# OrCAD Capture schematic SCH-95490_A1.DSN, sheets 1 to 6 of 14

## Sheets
1 01 TITLE PAGE: title: FRDM-MCXE31B; rev: A1; company: NXP Semiconductors; note: SCH-95490 PDF: SPF-95490; note: 6501 William Cannon Drive West; note: Austin, TX 78735-8598
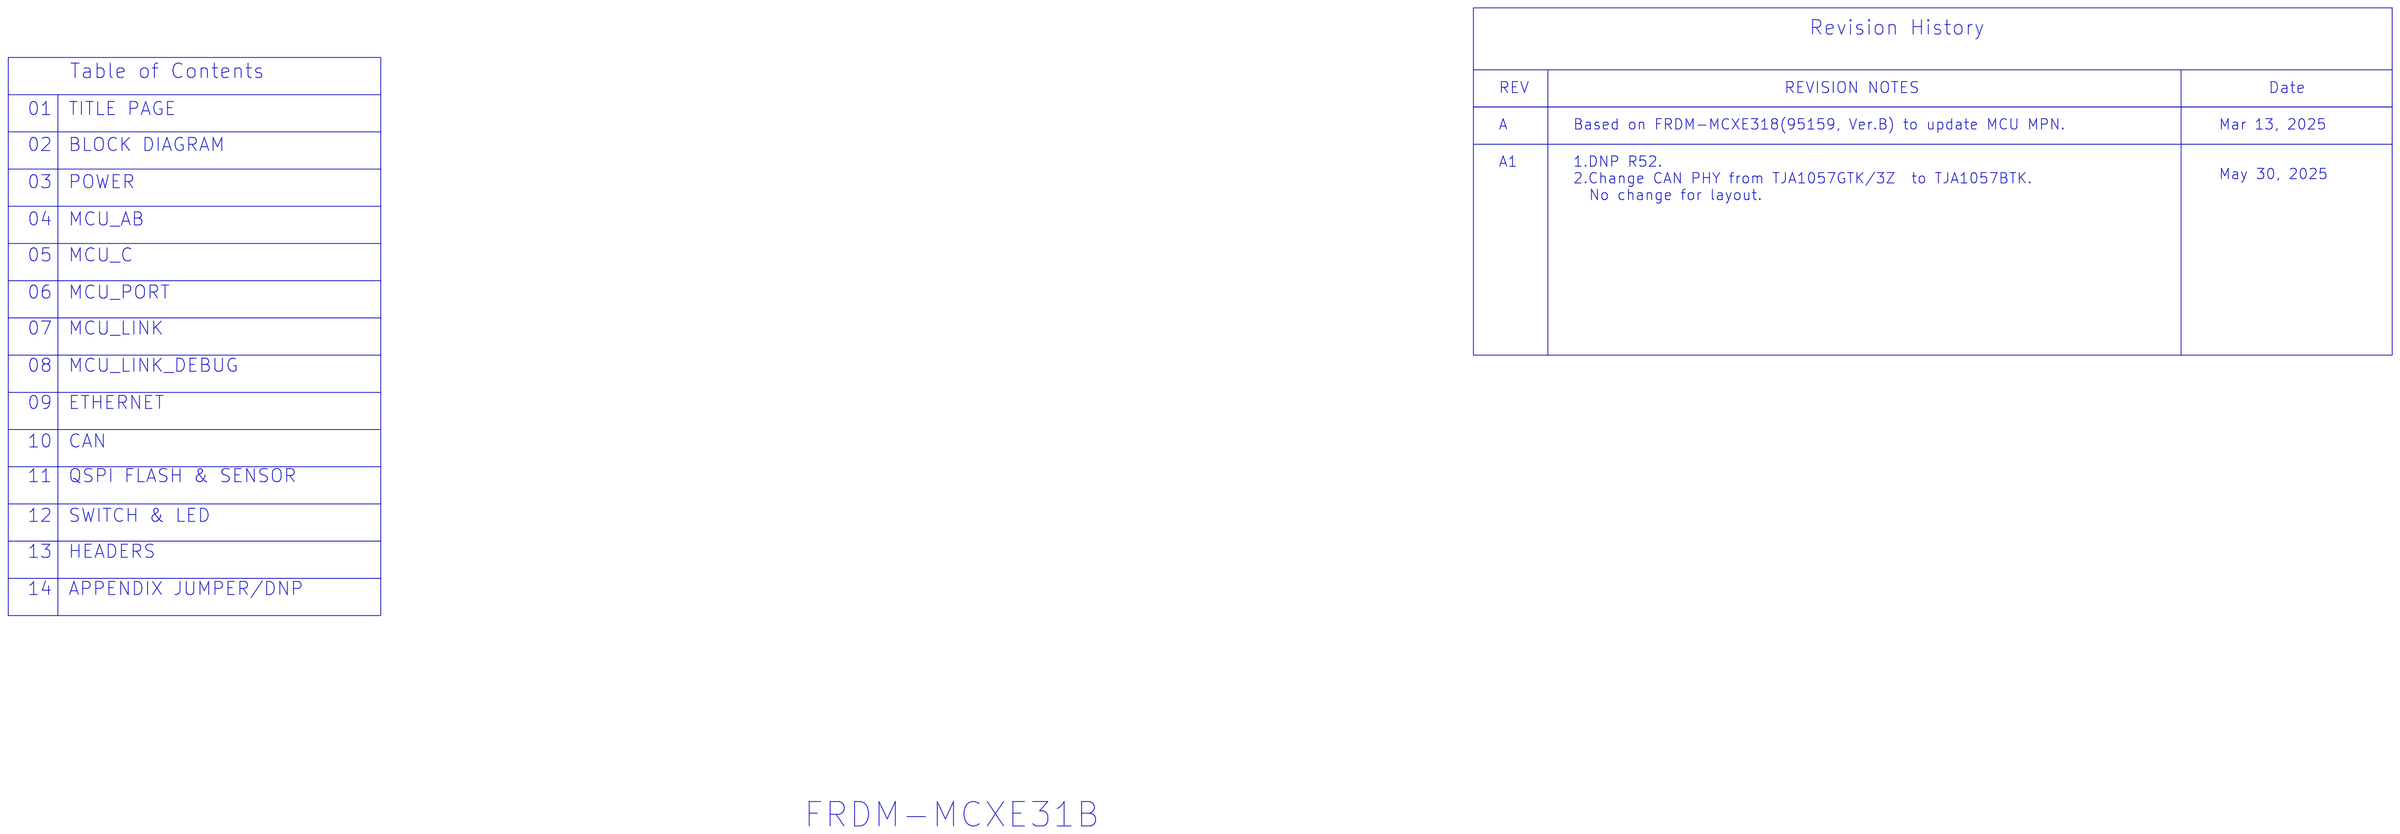
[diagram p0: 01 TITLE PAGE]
2 02 BLOCK DIAGRAM
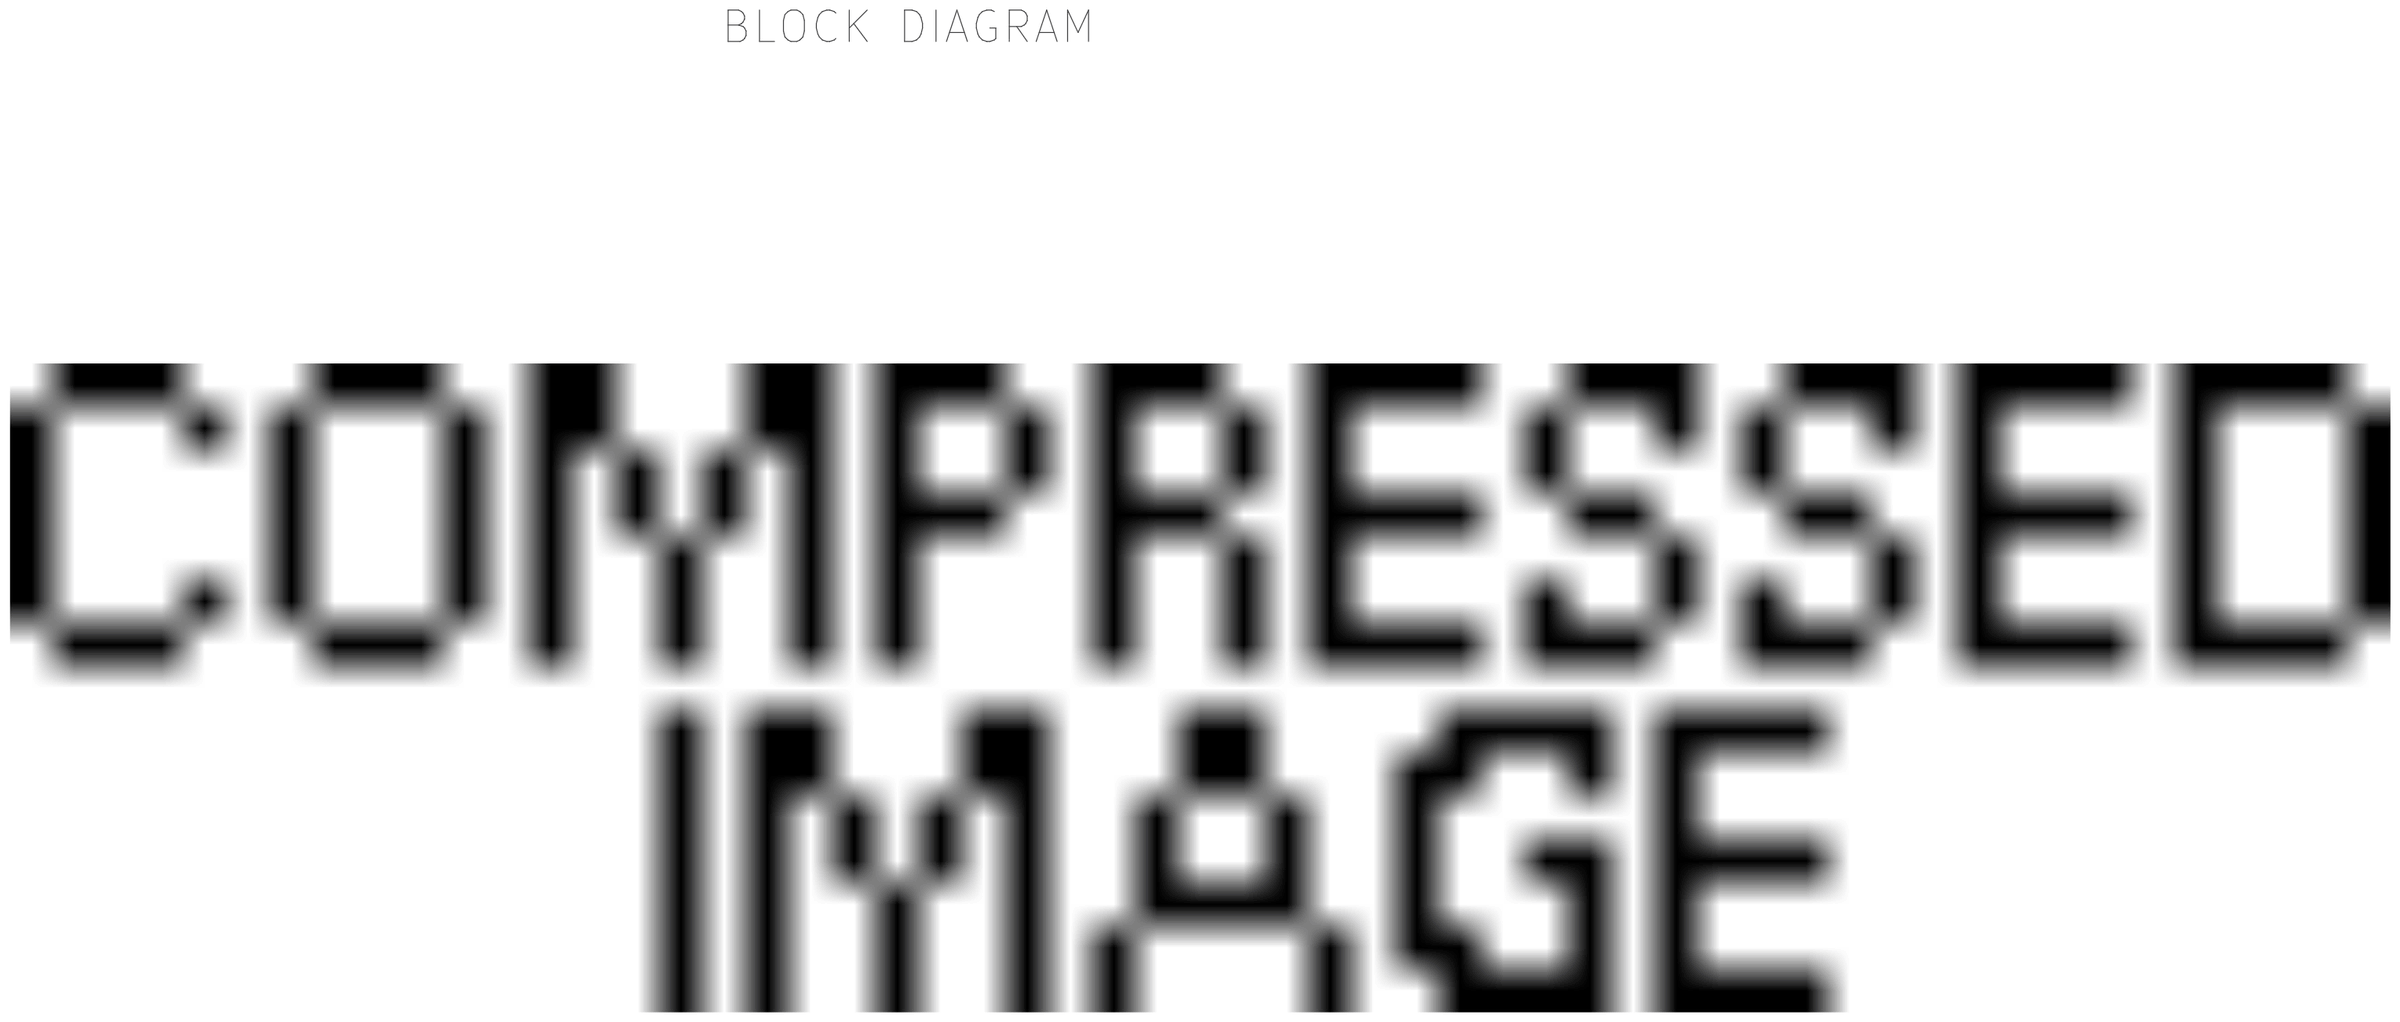
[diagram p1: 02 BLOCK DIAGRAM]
3 03 POWER: size C
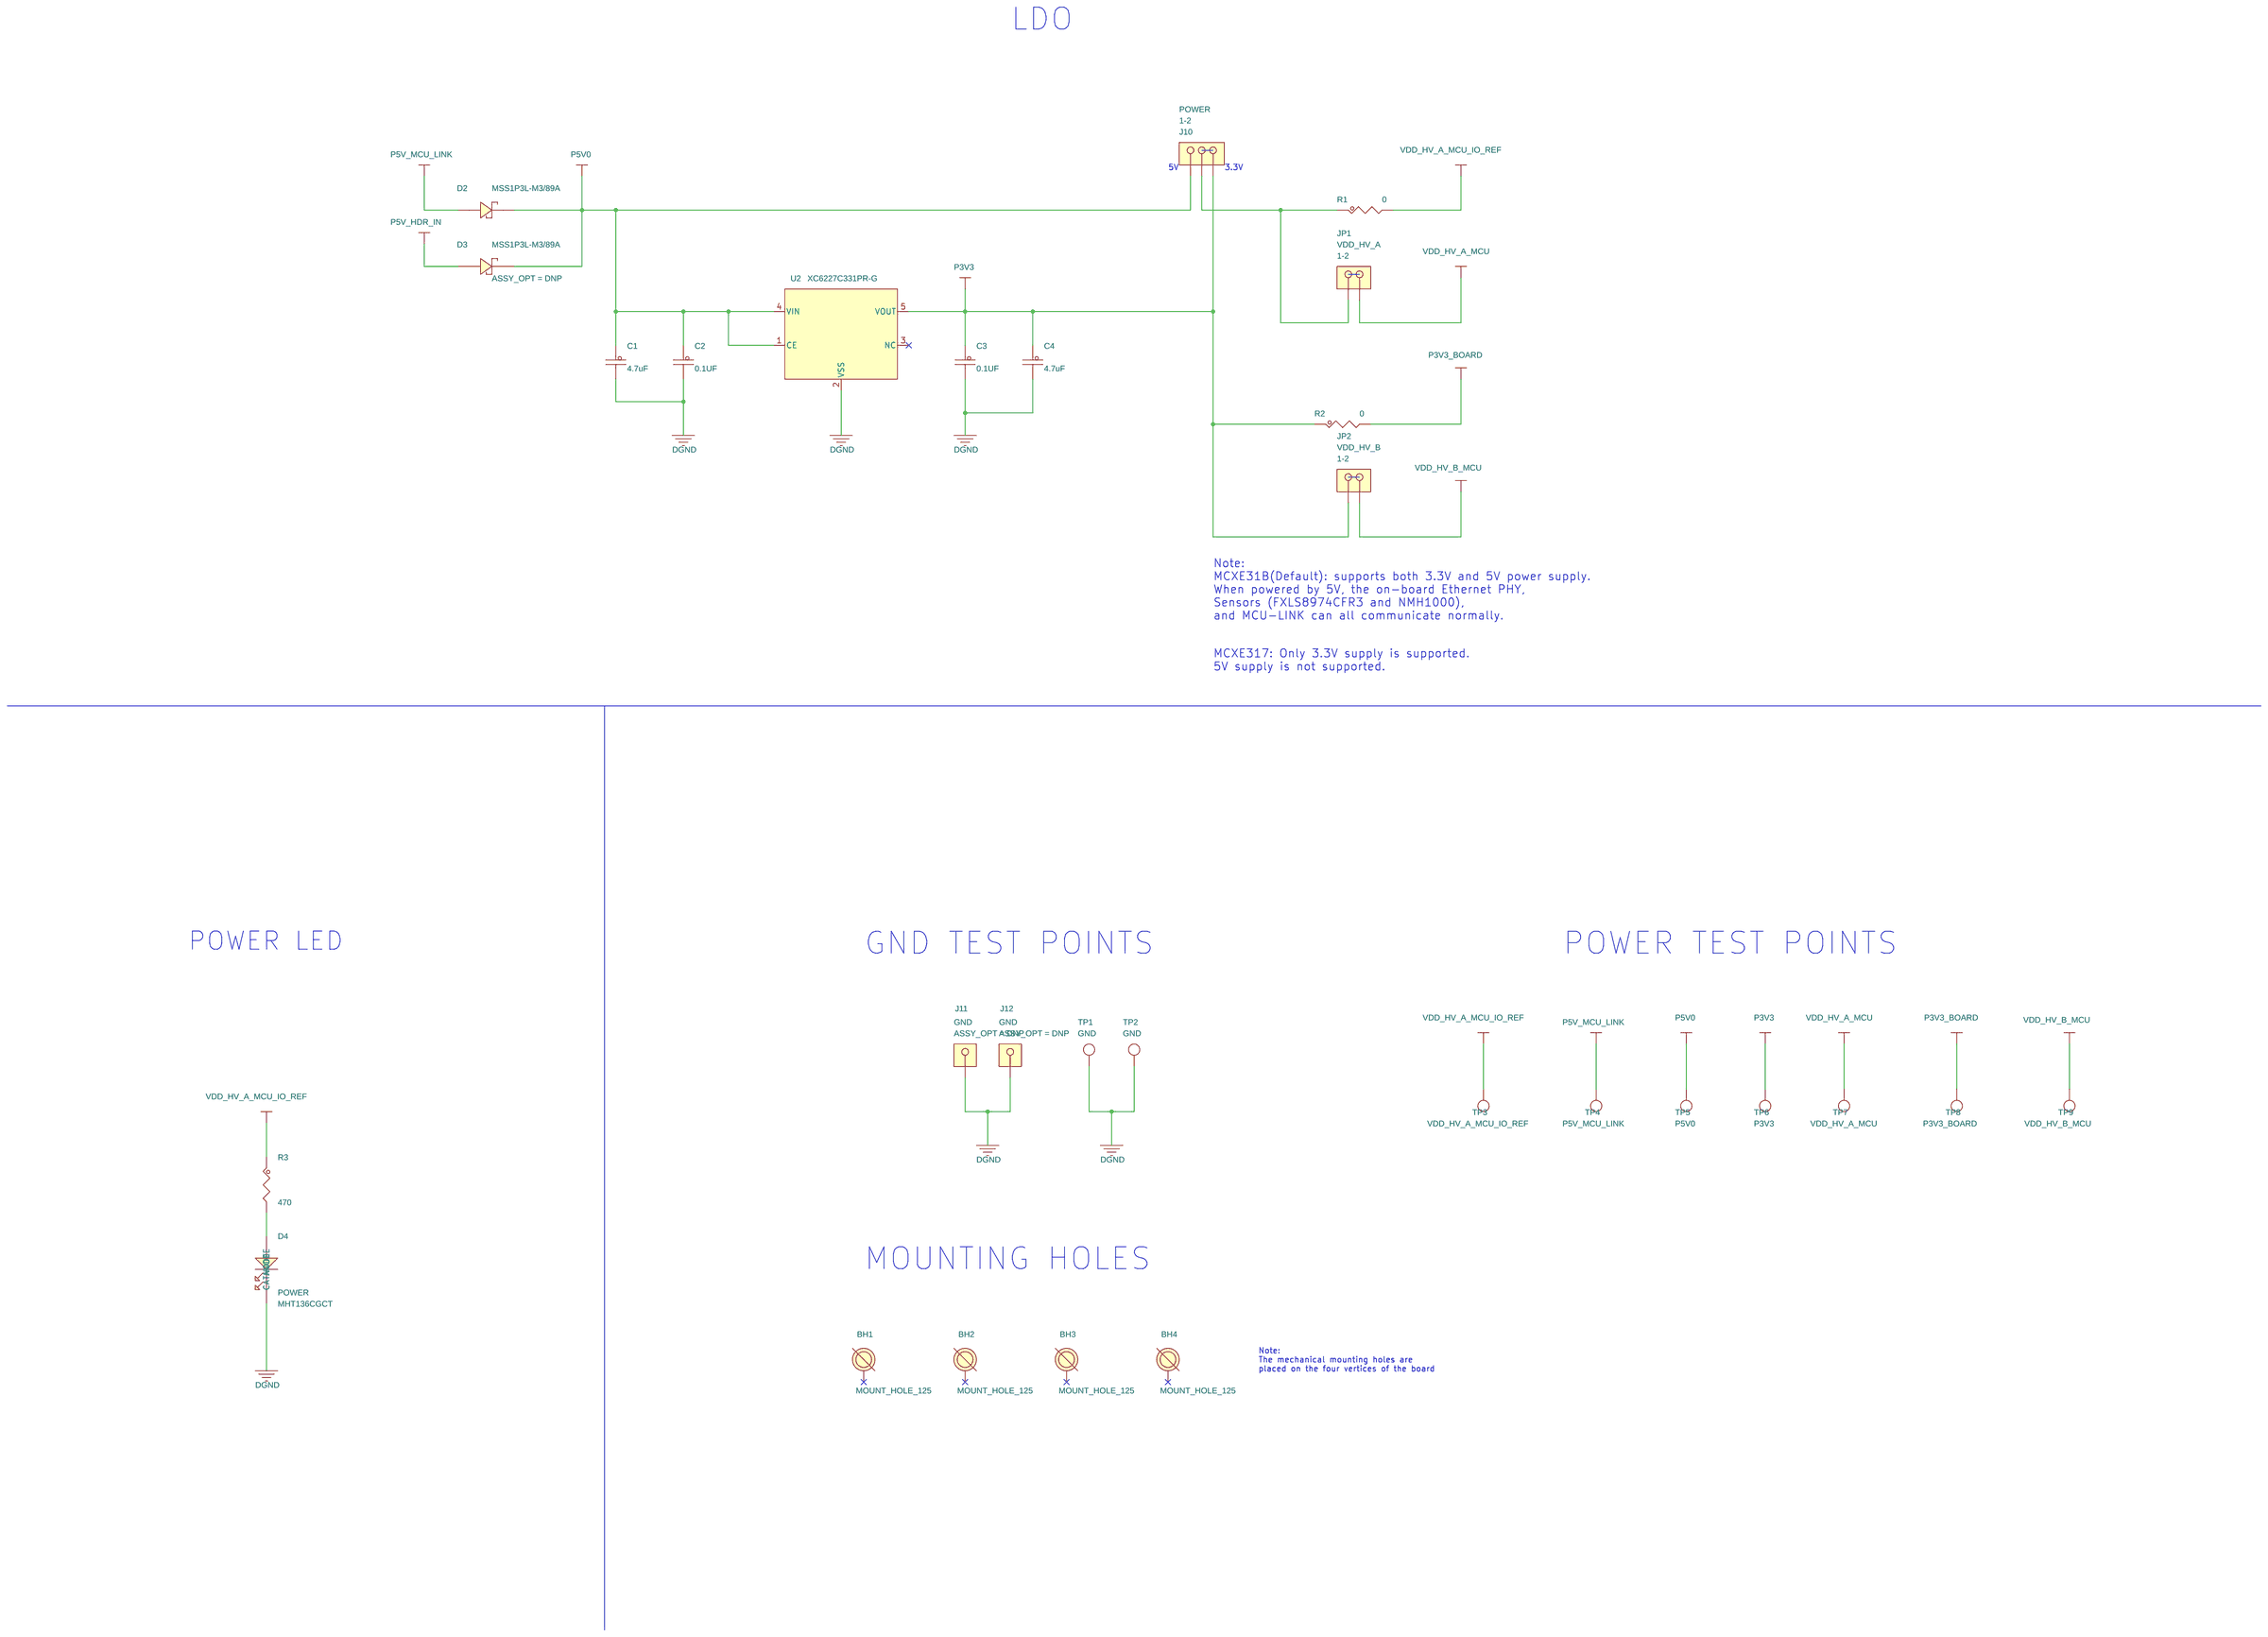
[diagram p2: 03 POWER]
4 04 MCU_AB: size C
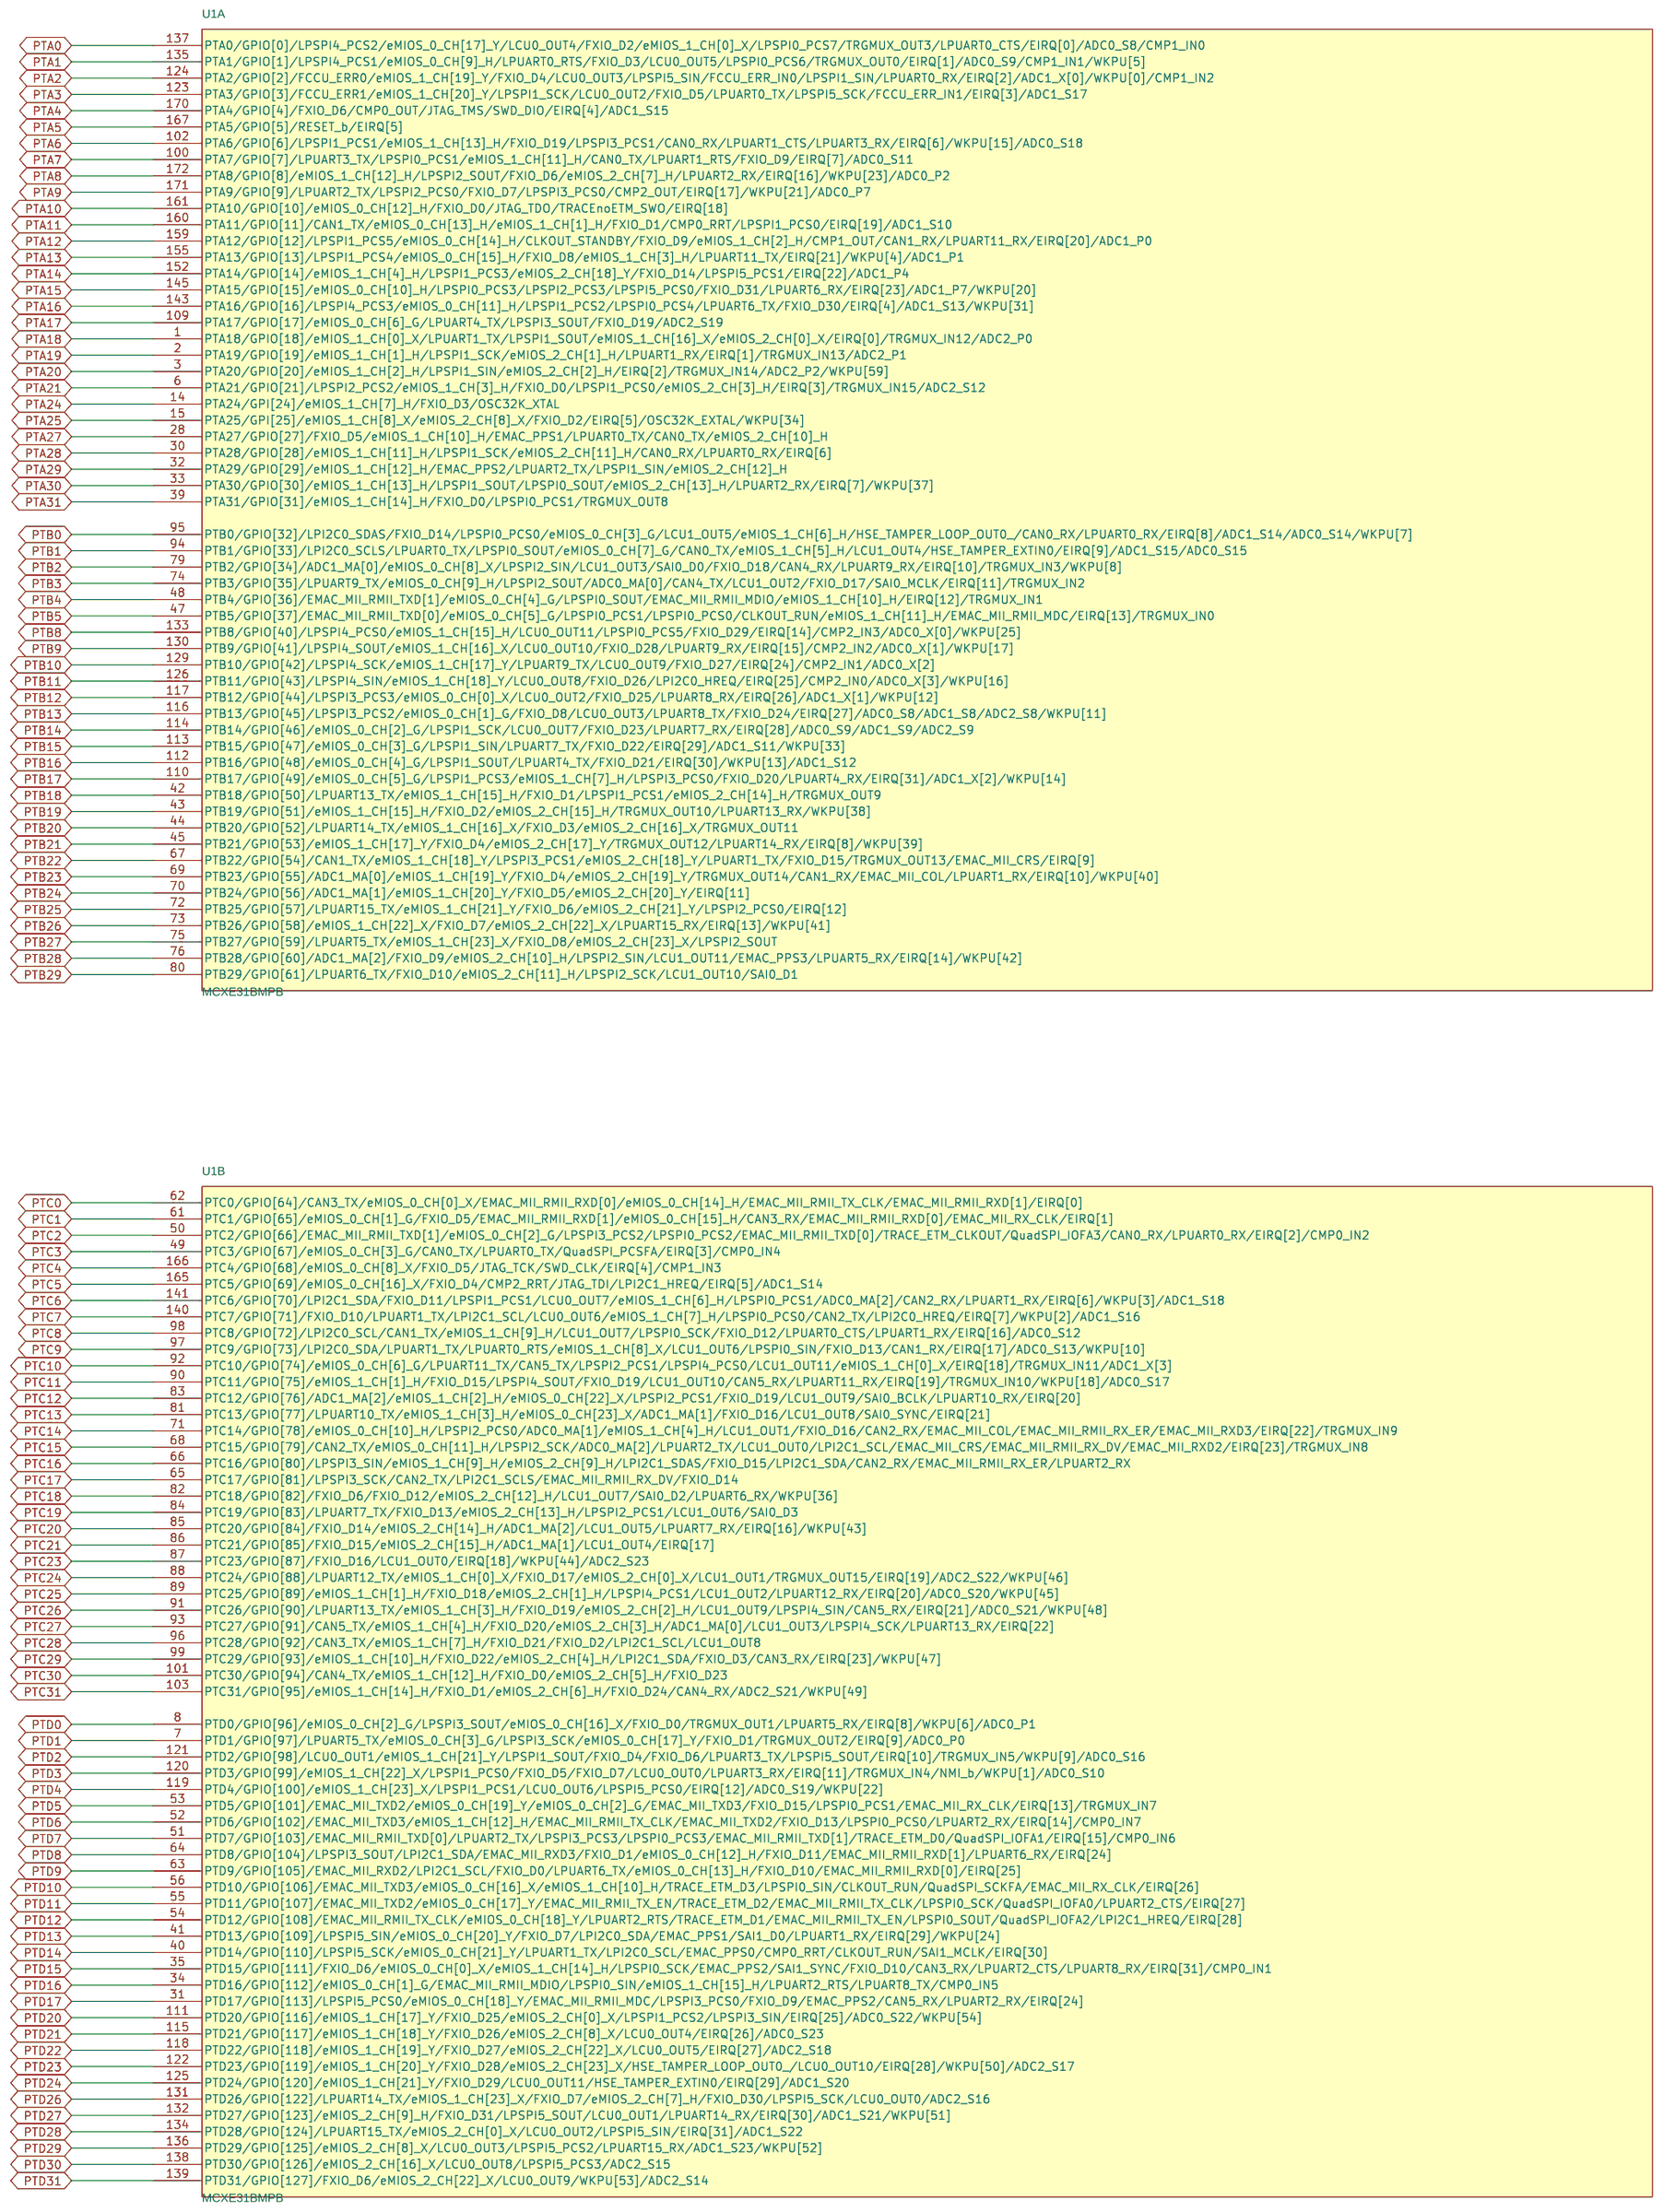
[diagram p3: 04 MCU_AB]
5 05 MCU_C: size C
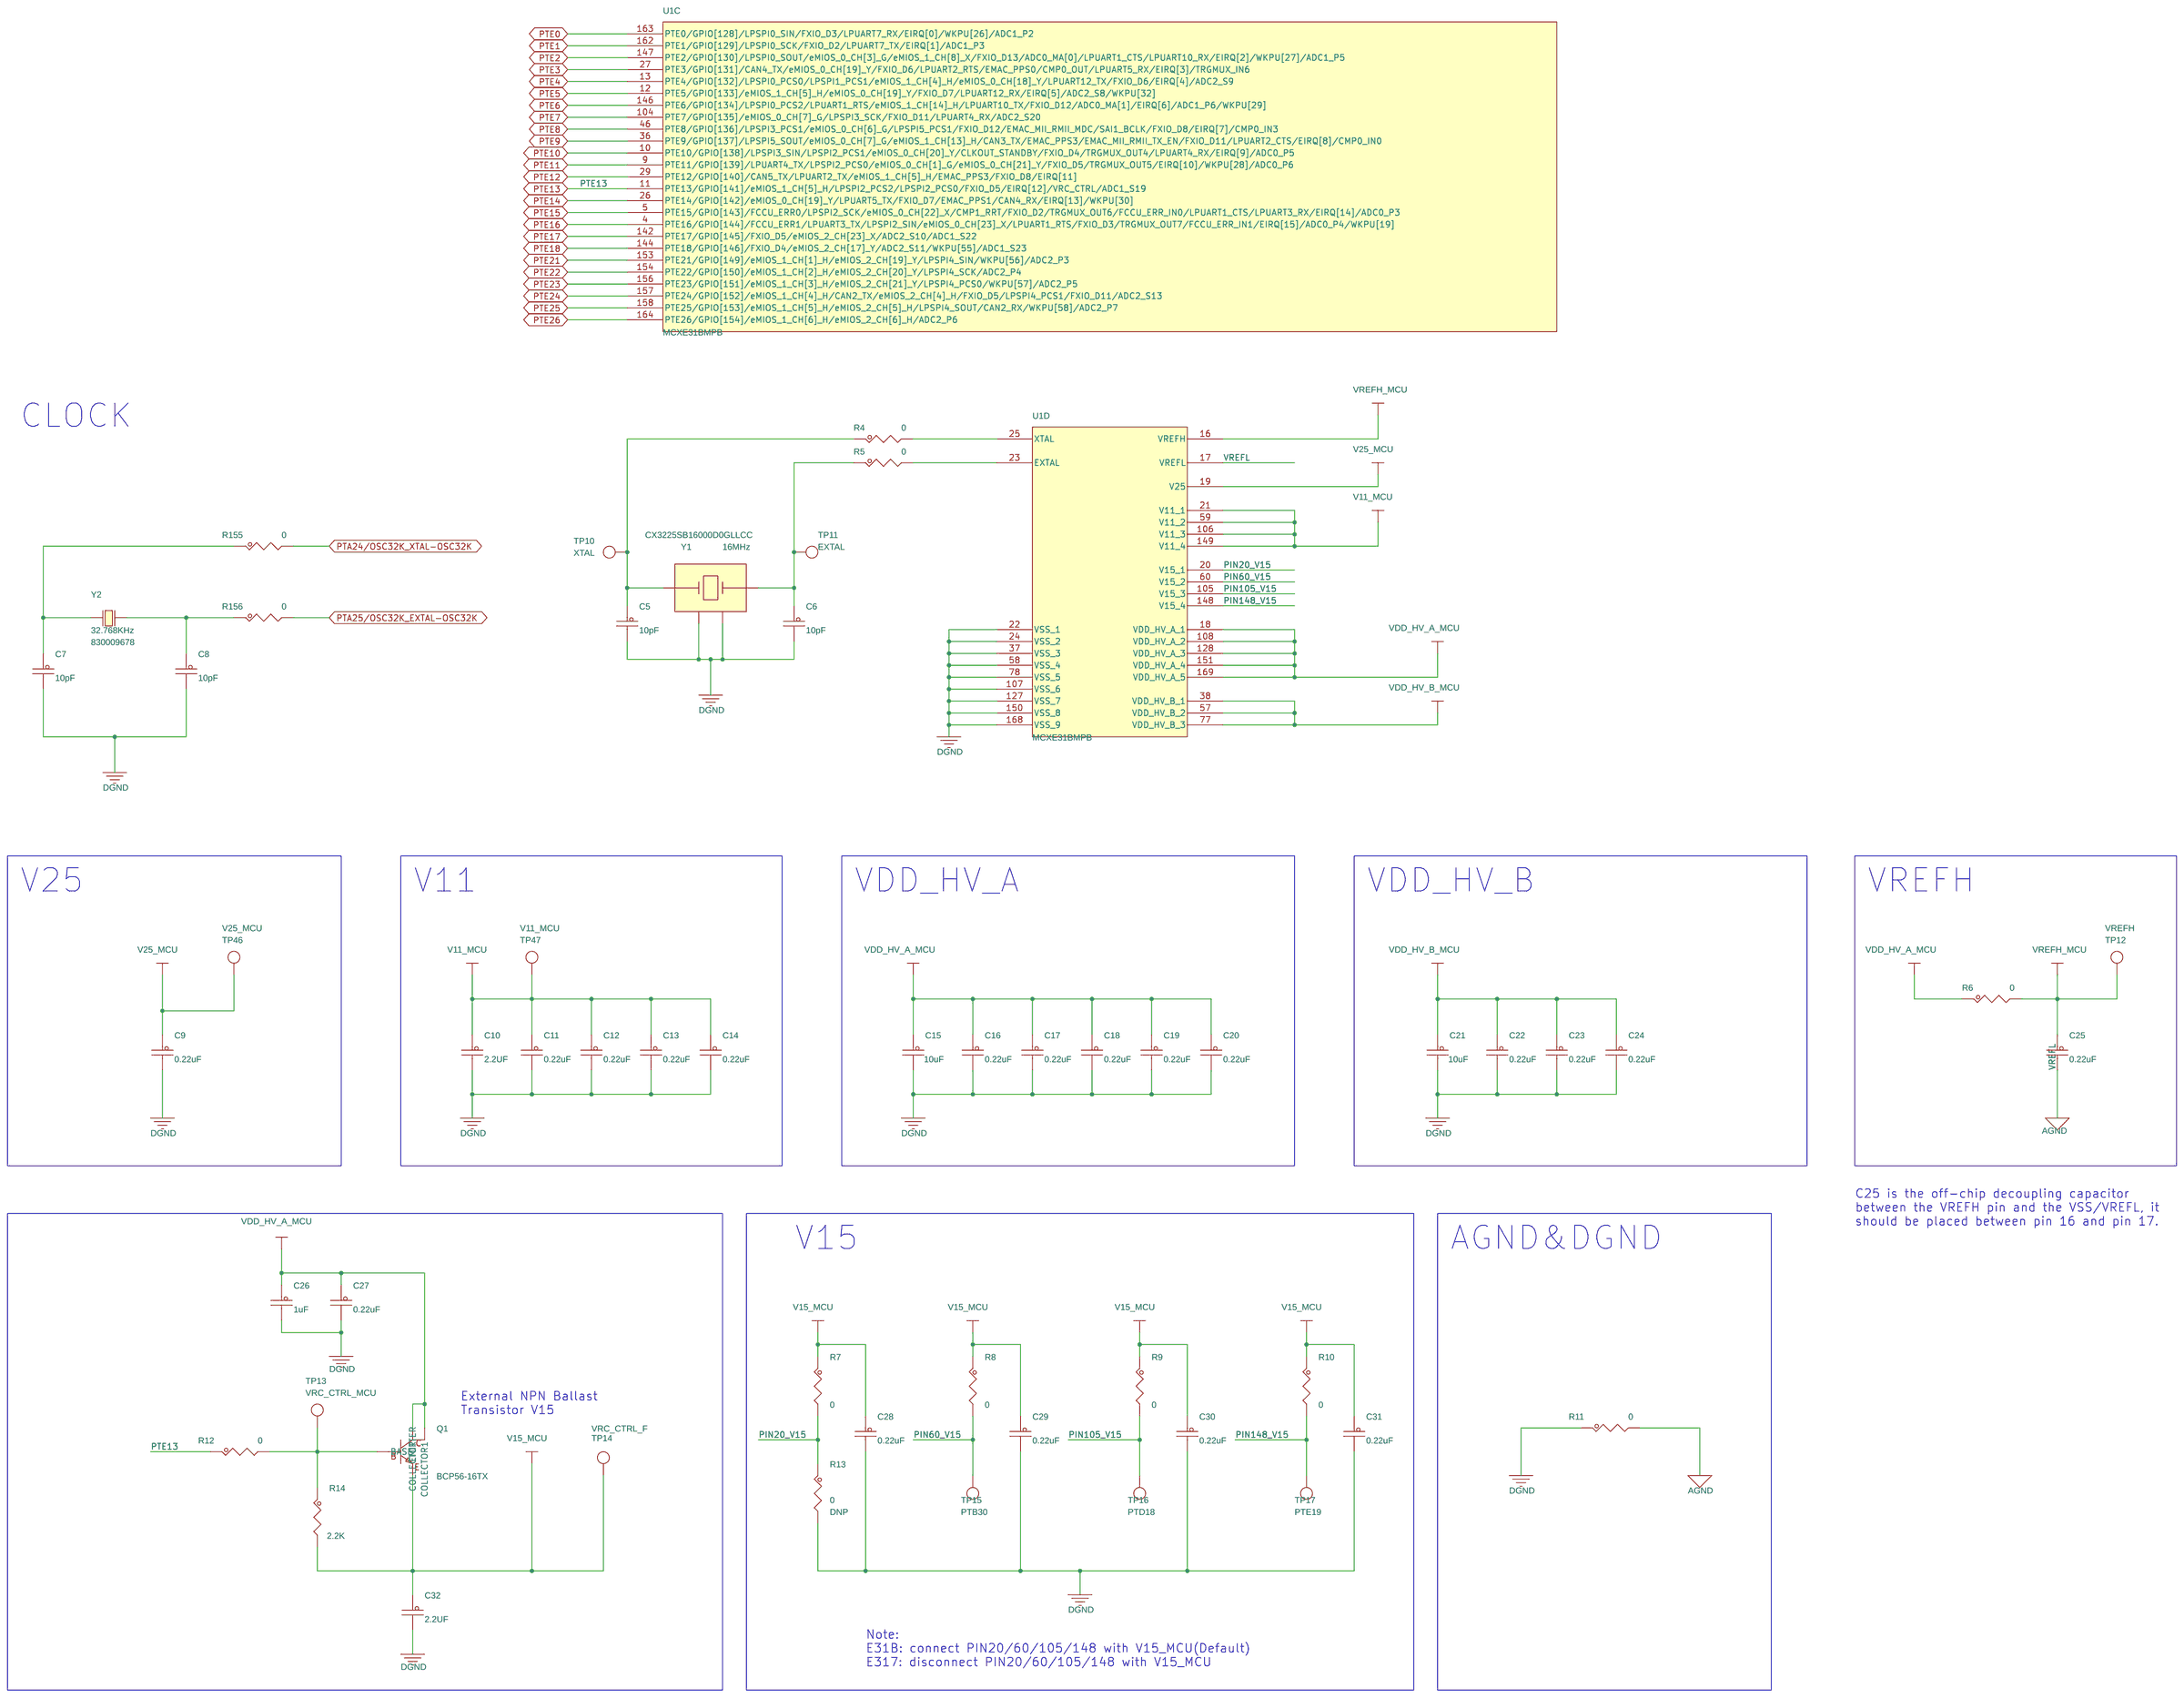
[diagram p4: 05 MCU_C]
6 06 MCU_PORT: size C
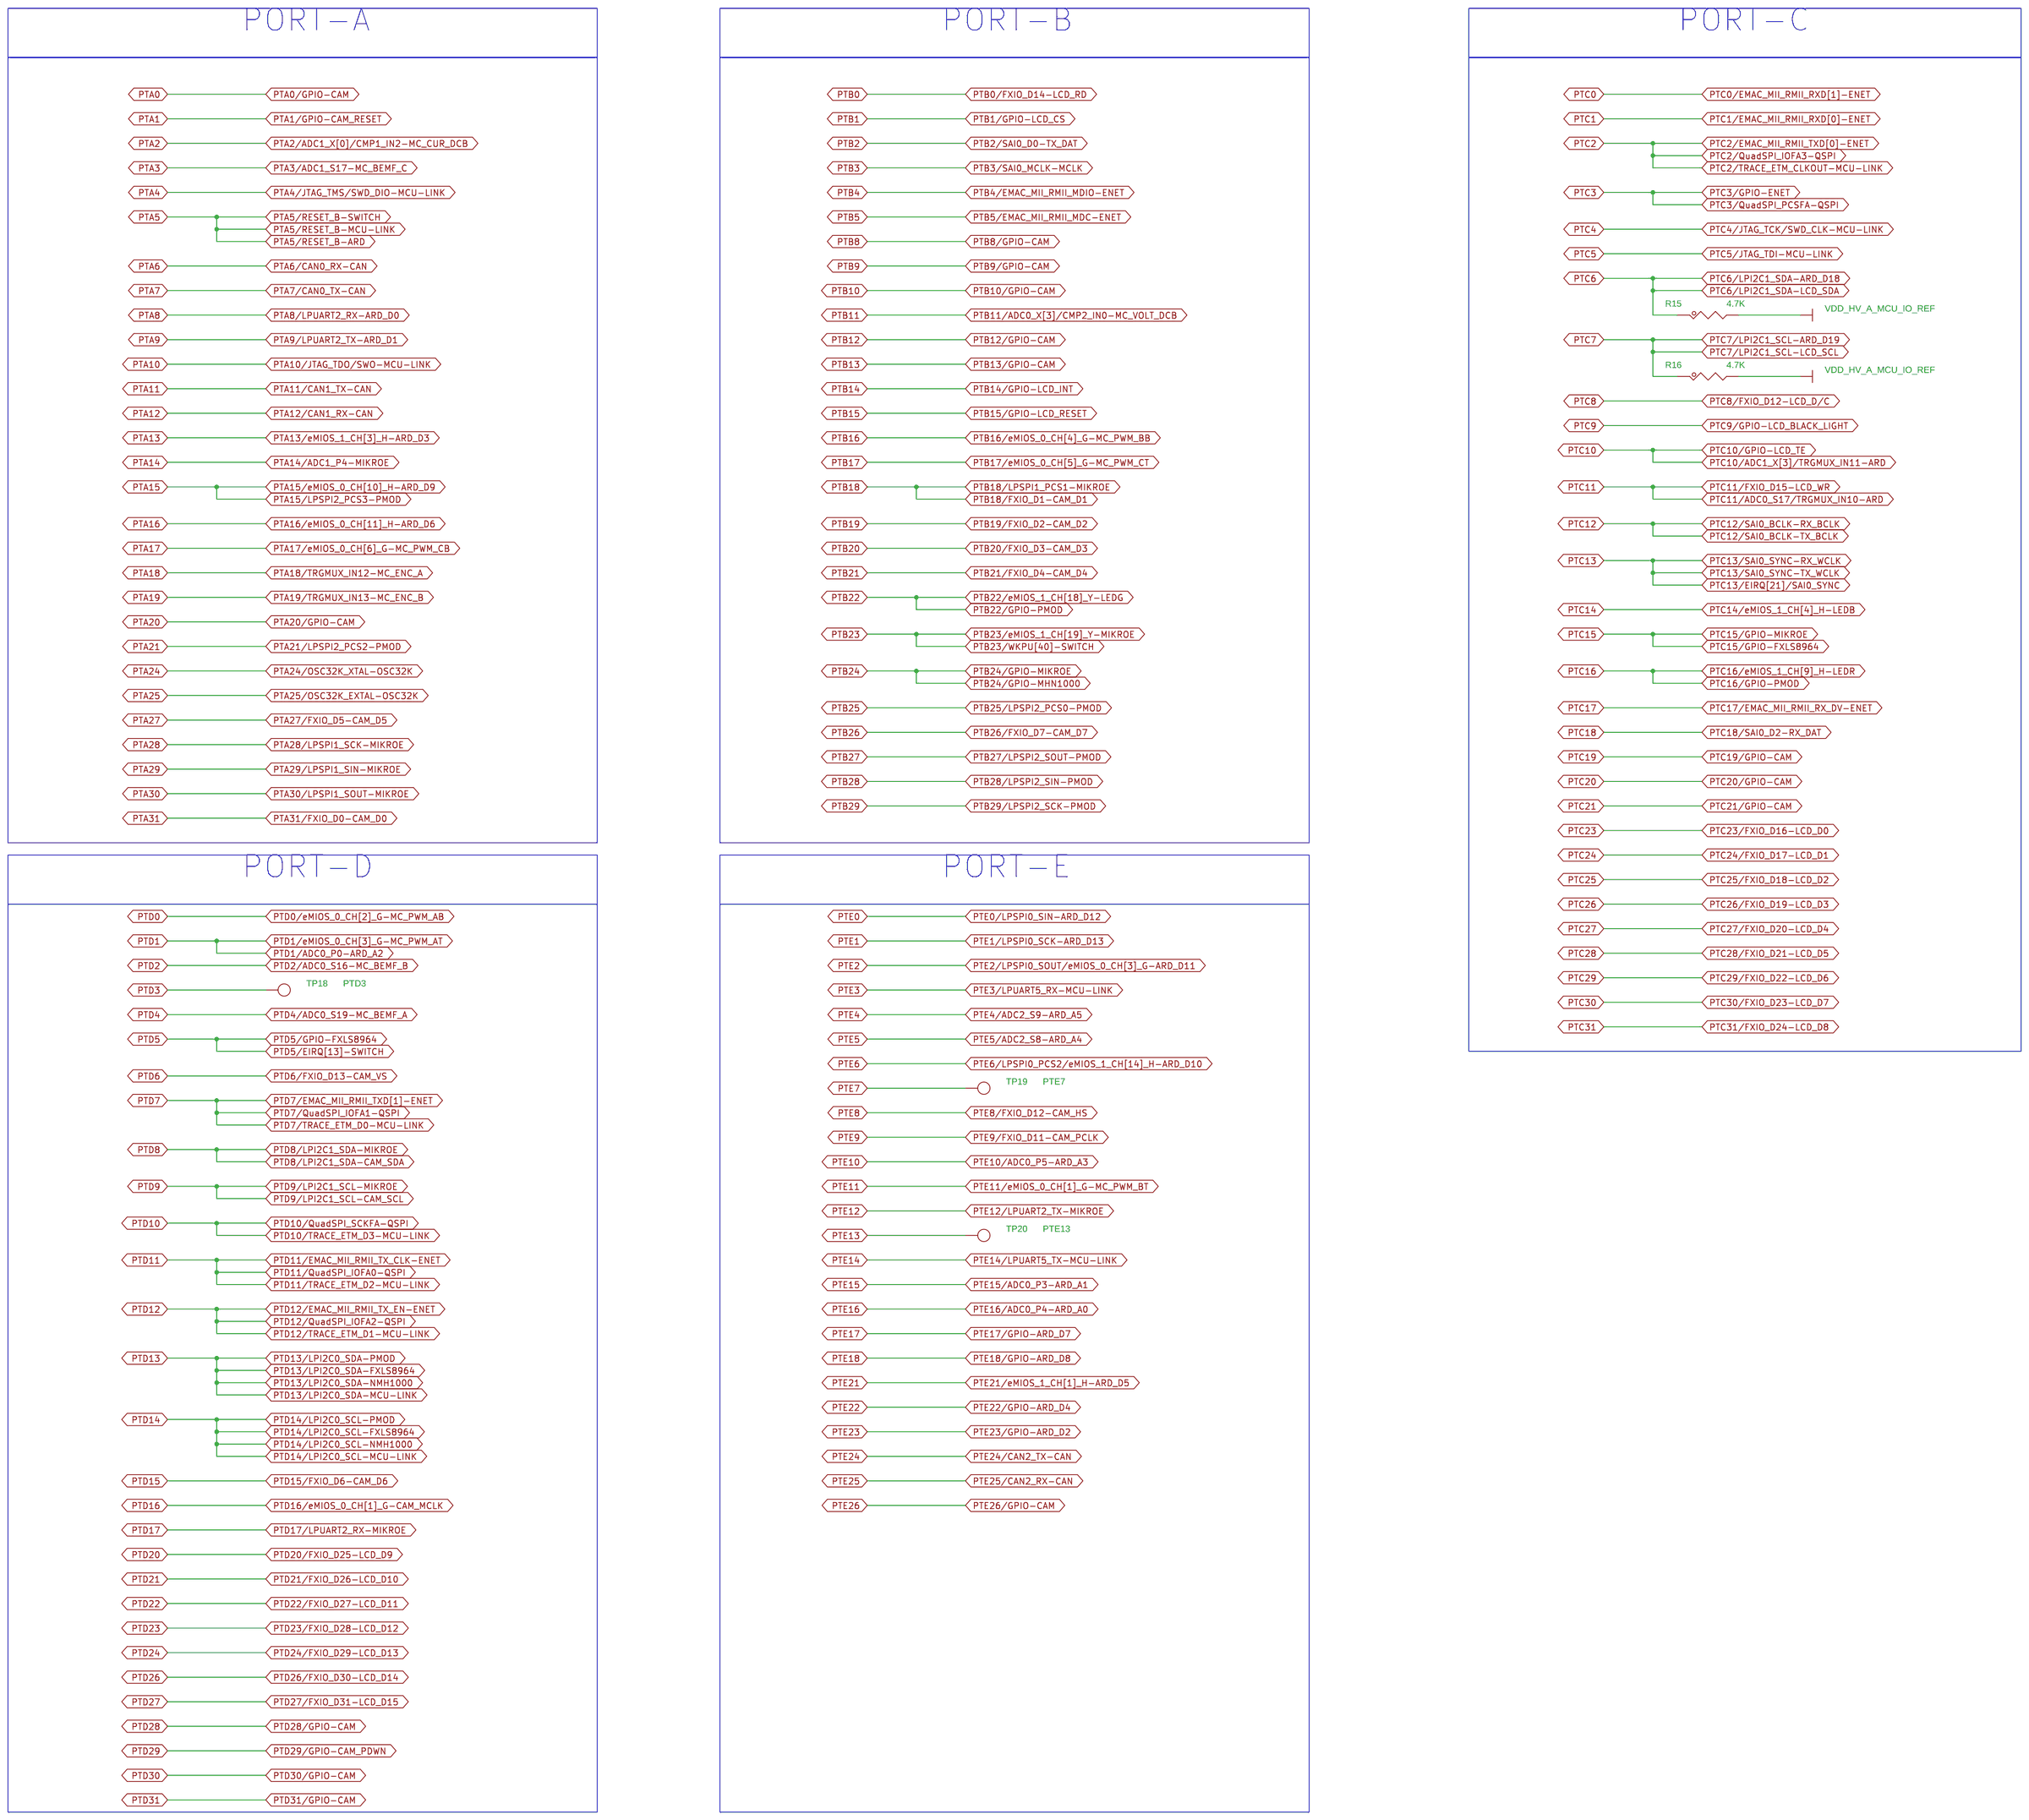
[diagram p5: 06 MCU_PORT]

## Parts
sheet 03 POWER
BH1  MOUNT_HOLE_125  [mh125-295]
BH2  MOUNT_HOLE_125  [mh125-295]
BH3  MOUNT_HOLE_125  [mh125-295]
BH4  MOUNT_HOLE_125  [mh125-295]
C1  4.7uF  [CC0603_OV]
C2  0.1UF  [CC0402_25]
C3  0.1UF  [CC0402_25]
C4  4.7uF  [CC0603_OV]
D2  MSS1P3L  [smb_2p7x1p4]
D3  MSS1P3L  [smb_2p7x1p4]
D4  YEL-GRN  [led_1x0p6_sm]
J10  HDR_1X3  [hdr103_330h]
J11  HDR 1X1  [HDR101]
J12  HDR 1X1  [HDR101]
JP1  HDR1X2  [hdr1x2_5p48x2p69]
JP2  HDR1X2  [hdr1x2_5p48x2p69]
R1  0  [RC0603_OV]
R2  0  [RC0603_OV]
R3  470  [RC0402_25]
TP1  TEST POINT  [tpad_040-fct]
TP2  TEST POINT  [tpad_040-fct]
TP3  TEST POINT  [tpad_040-fct]
TP4  TEST POINT  [tpad_040-fct]
TP5  TEST POINT  [tpad_040-fct]
TP6  TEST POINT  [tpad_040-fct]
TP7  TEST POINT  [tpad_040-fct]
TP8  TEST POINT  [tpad_040-fct]
TP9  TEST POINT  [tpad_040-fct]
U2  XC6227C331PR-G  [SOT89-5]
sheet 04 MCU_AB
U1  MCXE31BMPB  [hdqfp172_0P65_16X16_sm]  (sections A,B,C,D)
sheet 05 MCU_C
C5  10pF  [CC0402_25]
C6  10pF  [CC0402_25]
C7  10pF  [CC0402_25]
C8  10pF  [CC0402_25]
C9  0.22uF  [CC0402_25]
C10  2.2UF  [CC0402_25]
C11  0.22uF  [CC0402_25]
C12  0.22uF  [CC0402_25]
C13  0.22uF  [CC0402_25]
C14  0.22uF  [CC0402_25]
C15  10uF  [CC0603_OV]
C16  0.22uF  [CC0402_25]
C17  0.22uF  [CC0402_25]
C18  0.22uF  [CC0402_25]
C19  0.22uF  [CC0402_25]
C20  0.22uF  [CC0402_25]
C21  10uF  [CC0603_OV]
C22  0.22uF  [CC0402_25]
C23  0.22uF  [CC0402_25]
C24  0.22uF  [CC0402_25]
C25  0.22uF  [CC0402_25]
C26  1uF  [CC0402_25]
C27  0.22uF  [CC0402_25]
C28  0.22uF  [CC0402_25]
C29  0.22uF  [CC0402_25]
C30  0.22uF  [CC0402_25]
C31  0.22uF  [CC0402_25]
C32  2.2UF  [CC0402_25]
Q1  BCP56-16TX  [SOT223]
R4  0  [RC0603_OV]
R5  0  [RC0603_OV]
R6  0  [RC0603_OV]
R7  0  [RC0603_OV]
R8  0  [RC0603_OV]
R9  0  [RC0603_OV]
R10  0  [RC0603_OV]
R11  0  [RC0603_OV]
R12  0  [RC0603_OV]
R13  0  [RC0603_OV]
R14  2.2K  [RC0402_25]
R155  0  [RC0603_OV]
R156  0  [RC0603_OV]
TP10  TPAD_030  [TPAD_030]
TP11  TPAD_030  [TPAD_030]
TP12  TEST POINT  [tpad_040-fct]
TP13  TPAD_030  [TPAD_030]
TP14  TEST POINT  [tpad_040-fct]
TP15  TPAD_030  [TPAD_030]
TP16  TPAD_030  [TPAD_030]
TP17  TPAD_030  [TPAD_030]
TP46  TEST POINT  [tpad_040-fct]
TP47  TEST POINT  [tpad_040-fct]
Y1  16MHz  [xtal4_cx3225ca_sm]
Y2  32.768KHz  [XTAL2-3p2x1p5-SM]
sheet 06 MCU_PORT
R15  4.7K  [RC0402_25]
R16  4.7K  [RC0402_25]
TP18  TPAD_030  [TPAD_030]
TP19  TPAD_030  [TPAD_030]
TP20  TPAD_030  [TPAD_030]

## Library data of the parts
BH1-BH4 = MOUNT_HOLE: MOUNTING HOLE NON-PLATED DRILL 125MIL KEEP OUT 295MIL TH NO PART TO ORDER; AGILE_PN: 280-78093; CAD_APPROVED: Yes; HEIGHT: 0.1; MFG_NAME01: N/A; MFG_PN01: N/A; ROHS: Yes
C1 C4 = CAP_NP: CAP CER 4.7uF 10V 20% X5R 0603; 3D_Mechanical_Footprint_File: http://fcl.am.freescale.net/ALLEGRO/step/cc0603_ov.STEP; AGILE_PN: 150-81893; CAD_APPROVED: Yes; FPLIST: CC0603_OV,CC0603,0603_CC; HEIGHT: 0.87; MFG_NAME01: WURTH ELEKTRONIK; MFG_PN01: 885012106012; Package Size: 0603; Package Type: WCAP-CSGP_0603; ROHS: Yes; ROOM: CPU; Rated Voltage: 10V; SIGNAL_MODEL: DEFAULT_CAPACITOR_220000pF_2_1; TOL: 10%; Temp Range: -55C TO 85C; Tolerance: 20%; VOLTAGE: 10V; WVDC: 10V
C2 = CAP_NP: CAP CER 0.1UF 16V 10% X7R 0402; 3D_Mechanical_Footprint_File: http://fcl.am.freescale.net/ALLEGRO/step/cc0402_25.STEP; AGILE_PN: 150-75182; CAD_APPROVED: Yes; FPLIST: CC0402_25,CC0402_HD,0402_CC,CAPC0402_L,cc0402_lamp3; HEIGHT: 0.635mm; MFG_NAME01: Samsung Electro-Mechanics; MFG_PN01: CL05B104KO5NNNC; ROHS: NULL; Rated Voltage: 16V; Temp Range: -55C to +125C; Tolerance: 10%
C3 = CAP_NP: CAP CER 0.1UF 16V 10% X7R 0402; 3D_Mechanical_Footprint_File: http://fcl.am.freescale.net/ALLEGRO/step/cc0402_25.STEP; AGILE_PN: 150-75182; CAD_APPROVED: Yes; FPLIST: CC0402_25,CC0402_HD,0402_CC,CAPC0402_L,cc0402_lamp3; HEIGHT: 0.635mm; MFG_NAME01: Samsung Electro-Mechanics; MFG_PN01: CL05B104KO5NNNC; ROHS: NULL; Rated Voltage: 16V; SIGNAL_MODEL: DEFAULT_CAPACITOR_100000pF_2_1; TOL: 10%; Temp Range: -55C to +125C; Temp_Range: -55°C to +85°C; Tolerance: 10%; VOLTAGE: 16V
D2 = DIODE_SCHTKY: DIODE SCH 1A 30V MICROSMP SMT; 3D_Mechanical_Footprint_File: http://fcl.am.freescale.net/ALLEGRO/step/smb_2p7x1p4.step; AGILE_PN: 480-76978; CAD_APPROVED: Yes; HEIGHT: 0.73; MFG_NAME01: VISHAY INTERTECHNOLOGY; MFG_PN01: MSS1P3L-M3/89A; Rated Voltage: 30V
D3 = DIODE_SCHTKY: DIODE SCH 1A 30V MICROSMP SMT; 3D_Mechanical_Footprint_File: http://fcl.am.freescale.net/ALLEGRO/step/smb_2p7x1p4.step; AGILE_PN: 480-76978; ASSY_OPT: DNP; CAD_APPROVED: Yes; HEIGHT: 0.73; MFG_NAME01: VISHAY INTERTECHNOLOGY; MFG_PN01: MSS1P3L-M3/89A; Rated Voltage: 30V
D4 = LED: LED YEL-GRN SGL 25mA SMT 0402; 3D_Mechanical_Footprint_File: http://fcl.am.freescale.net/ALLEGRO/step/led_1x0p6_sm_14h.step; AGILE_PN: 370-76900; CAD_APPROVED: YES; HEIGHT: 0.35mm; MFG_NAME01: Lianyungang Meihua Electronics Technology Co.,Ltd; MFG_PN01: MHT136CGCT; Package Size: 1 x 0.5 x 0.3 mm; Rated Voltage: 1.7-2.2V@5mA; SILK: POWER; Temp Range: -35°C to +85°C; VOLTAGE: 1.7-2.2V@5mA
J10 = CONN_HDR_3X1: HDR 1X3 TH 100MIL SP 330H AU 98L; 3D_Mechanical_Footprint_File: http://fcl.am.freescale.net/ALLEGRO/step/hdr103_330h.STEP; AGILE_PN: 210-75442; CAD_APPROVED: Yes; HEIGHT: 8.59; JUMPER: 1-2; MFG_NAME01: SAMTEC; MFG_PN01: HTSW-103-07-S-S; Package Type: HEADER; ROHS: NULL; SILK: POWER; Temp Range: -55°C to +125°C
J11 J12 = CONN_HDR_1X1: HDR 1X1 TH -- 330H AU 100L; 3D_Mechanical_Footprint_File: http://fcl.am.freescale.net/ALLEGRO/step/hdr101.STEP; AGILE_PN: 210-75767; ASSY_OPT: DNP; CAD_APPROVED: Yes; HEIGHT: 8.585; MFG_NAME01: SAMTEC; MFG_PN01: HTSW-101-07-SM-S; Package Size: 2.54 x 2.54 mm; ROHS: Yes; SILK: GND
JP1 = CONN_HDR_2X1: HDR 1X2 TH 100MIL SP 342H AU 118L; 3D_Mechanical_Footprint_File: http://fcl.am.freescale.net/ALLEGRO/step/hdr1x2_5p48x2p69.STEP; AGILE_PN: 210-80468; CAD_APPROVED: Yes; HEIGHT: 8.69; JUMPER: 1-2; MFG_NAME01: WURTH ELEKTRONIK EISOS GMBH & CO. KG (ELECTRONIC & ELECTROMEHANICAL COMP); MFG_PN01: 61300211121; Package Type: TH; ROHS: Yes; SILK: VDD_HV_A; Temp Range: -40°C to 105°C
JP2 = CONN_HDR_2X1: HDR 1X2 TH 100MIL SP 342H AU 118L; 3D_Mechanical_Footprint_File: http://fcl.am.freescale.net/ALLEGRO/step/hdr1x2_5p48x2p69.STEP; AGILE_PN: 210-80468; CAD_APPROVED: Yes; HEIGHT: 8.69; JUMPER: 1-2; MFG_NAME01: WURTH ELEKTRONIK EISOS GMBH & CO. KG (ELECTRONIC & ELECTROMEHANICAL COMP); MFG_PN01: 61300211121; Package Type: TH; ROHS: Yes; SILK: VDD_HV_B; Temp Range: -40°C to 105°C
R1 R2 R4-R12 R155 R156 = RES: RES MF ZERO OHM 1/10W -- 0603; AGILE_PN: 470-80866; CAD_APPROVED: Yes; FPLIST: RC0603_OV,RC0603,R603-X2,r603-x2_b,0603_CC,IND_0603HP_NSP,CC0603_OV_NSP; HEIGHT: 0.6; MFG_NAME01: VISHAY; MFG_PN01: CRCW06030000Z0EAC; ROHS: NULL; Temp Range: –55 °C to +155 °C; VOLTAGE: 1/16W
R3 = RES: RES MF 470 OHM 1/16W 5% 0402; AGILE_PN: 470-30315; CAD_APPROVED: Yes; FPLIST: RC0402_25,RC0402_HD,0402_CC; HEIGHT: 0.45; MFG_NAME01: PANASONIC; MFG_PN01: ERJ2GEJ471X; ROHS: Yes; Tolerance: 5%
TP1 TP2 = TESTLOOP: TEST POINT PAD 40MIL DIA SMT, NO PART TO ORDER; AGILE_PN: 211-10189; CAD_APPROVED: yes; HEIGHT: 0.1MM; MFG_NAME01: NO PART TO ORDER; MFG_PN01: NO PART TO ORDER; ROHS: NULL; SILK: GND
TP3 = TESTLOOP: TEST POINT PAD 40MIL DIA SMT, NO PART TO ORDER; AGILE_PN: 211-10189; CAD_APPROVED: yes; HEIGHT: 0.1MM; MFG_NAME01: NO PART TO ORDER; MFG_PN01: NO PART TO ORDER; ROHS: NULL; SILK: VDD_HV_A_MCU_IO_REF
TP4 = TESTLOOP: TEST POINT PAD 40MIL DIA SMT, NO PART TO ORDER; AGILE_PN: 211-10189; CAD_APPROVED: yes; HEIGHT: 0.1MM; MFG_NAME01: NO PART TO ORDER; MFG_PN01: NO PART TO ORDER; ROHS: NULL; SILK: P5V_MCU_LINK
TP5 = TESTLOOP: TEST POINT PAD 40MIL DIA SMT, NO PART TO ORDER; AGILE_PN: 211-10189; CAD_APPROVED: yes; HEIGHT: 0.1MM; MFG_NAME01: NO PART TO ORDER; MFG_PN01: NO PART TO ORDER; ROHS: NULL; SILK: P5V0
TP6 = TESTLOOP: TEST POINT PAD 40MIL DIA SMT, NO PART TO ORDER; AGILE_PN: 211-10189; CAD_APPROVED: yes; HEIGHT: 0.1MM; MFG_NAME01: NO PART TO ORDER; MFG_PN01: NO PART TO ORDER; ROHS: NULL; SILK: P3V3
TP7 = TESTLOOP: TEST POINT PAD 40MIL DIA SMT, NO PART TO ORDER; AGILE_PN: 211-10189; CAD_APPROVED: yes; HEIGHT: 0.1MM; MFG_NAME01: NO PART TO ORDER; MFG_PN01: NO PART TO ORDER; ROHS: NULL; SILK: VDD_HV_A_MCU
TP8 = TESTLOOP: TEST POINT PAD 40MIL DIA SMT, NO PART TO ORDER; AGILE_PN: 211-10189; CAD_APPROVED: yes; HEIGHT: 0.1MM; MFG_NAME01: NO PART TO ORDER; MFG_PN01: NO PART TO ORDER; ROHS: NULL; SILK: P3V3_BOARD
TP9 = TESTLOOP: TEST POINT PAD 40MIL DIA SMT, NO PART TO ORDER; AGILE_PN: 211-10189; CAD_APPROVED: yes; HEIGHT: 0.1MM; MFG_NAME01: NO PART TO ORDER; MFG_PN01: NO PART TO ORDER; ROHS: NULL; SILK: VDD_HV_B_MCU
U2 = XC6227C_5P: IC VREG LDO  3.3V 0.7A 1.7-6.0V SOT-89-5; 3D_Mechanical_Footprint_File: http://fcl.am.freescale.net/ALLEGRO/step/sot89-5.STEP; AGILE_PN: 315-80827; CAD_APPROVED: Yes; HEIGHT: 1.6mm; MFG_NAME01: TOREX; ROHS: NULL; Temp Range: -40°C to 85°C; VOLTAGE: 1.7V ~ 6.0V
U1 = MCXE318MPB_172P: IC MCU 4M FLASH 2.97-5.5V 160MHZ HDQFP172; 3D_Mechanical_Footprint_File: http://fcl.am.freescale.net/ALLEGRO/step/hdqfp172_0P65_16X16_sm.STEP; AGILE_PN: TMP-CIP-19819; CAD_APPROVED: Yes; HEIGHT: 1.75mm; MFG_NAME01: NXP SEMICONDUCTOR; PRE_APN: 344-10070; ROHS: NULL; Temp Range: -40°C to +125°C
C5-C8 = CAP_NP: CAP CER 10pF 50V 5% C0G AEC-Q200 0402; 3D_Mechanical_Footprint_File: http://fcl.am.freescale.net/ALLEGRO/step/cc0402_25.STEP; AGILE_PN: 150-79023; CAD_APPROVED: Yes; FPLIST: CC0402_25,CC0402_HD,0402_CC,capc0402_l; HEIGHT: 0.55; MFG_NAME01: MURATA; MFG_PN01: GCM1555C1H100JA16; Package Size: 0402 [1005 Metric]; Package Type: SMD/SMT; ROHS: Yes; Rated Voltage: 50V; Temp Range: -55C to +125C; Tolerance: 5%; VOLTAGE: 50V
C9 C11-C14 C16-C20 C22-C25 C27-C31 = CAP_NP: CAP CER 0.22UF 16V 10% X7R 0402; 3D_Mechanical_Footprint_File: http://fcl.am.freescale.net/ALLEGRO/step/cc0402_25.STEP; AGILE_PN: 150-78886; CAD_APPROVED: Yes; FPLIST: CC0402_25,CC0402_HD,0402_CC; HEIGHT: 0.55; MFG_NAME01: FENGHUA; MFG_PN01: 0402B224K160NT; Package Size: 0402 [1005 Metric]; Package Type: SMD/SMT; ROHS: Yes; Rated Voltage: 16V; Temp Range: -55C to +125C; Tolerance: 10%; VOLTAGE: 16V
C10 C32 = CAP_NP: CAP CER 2.2UF 10V 20% X5R 0402; 3D_Mechanical_Footprint_File: http://fcl.am.freescale.net/ALLEGRO/step/cc0402_25.STEP; AGILE_PN: 150-79665; CAD_APPROVED: Yes; FPLIST: CC0402_25,CC0402_HD,0402_CC,capc0402_l; HEIGHT: 0.55; MFG_NAME01: KEMET; MFG_PN01: C0402C225M8PACTU; ROHS: Yes; Rated Voltage: 10V; Temp Range: -55C to +85C; Tolerance: 20%
C15 C21 = CAP_NP: CAP CER 10uF 25V 20% X5R 0603; AGILE_PN: 150-79272; CAD_APPROVED: Yes; FPLIST: CC0603_OV,CC0603,0603_cc_tol; HEIGHT: 1; MFG_NAME01: MURATA; MFG_PN01: GRM188R61E106MA73D; Package Size: 0603; ROHS: Yes; Rated Voltage: 25V; Temp Range: -55C to +85C; Tolerance: 20%
C26 = CAP_NP: CAP CER 1.0uF 16V 10% X6S 0402; AGILE_PN: 150-80262; CAD_APPROVED: Yes; FPLIST: CC0402_25,CC0402_HD,0402_CC,capc0402_l; HEIGHT: 0.55; MFG_NAME01: MURATA; MFG_PN01: GRM155C81C105KE11D; ROHS: Yes; Rated Voltage: 16V; SIGNAL_MODEL: DEFAULT_CAPACITOR_1e+06pF_2_1; Temp Range: -55C to +105C; Temp_Range: -55°C to +125°C; Tolerance: 10%; VOLTAGE: 16V
Q1 = TRAN_NPN_SOT223: TRANS NPN 80V 1A AEC-Q101 SOT223; AGILE_PN: 480-79956; CAD_APPROVED: Yes; HEIGHT: 1.8; MFG_NAME01: NEXPERIA; ROHS: Yes; Temp Range: -55°C ~ 150°C; Temp_Range: -55°C ~ 150°C
R13 = RES: RES MF ZERO OHM 1/10W -- 0603; AGILE_PN: 470-80866; ASSY_OPT: DNP; CAD_APPROVED: Yes; FPLIST: RC0603_OV,RC0603,R603-X2,r603-x2_b,0603_CC,IND_0603HP_NSP,CC0603_OV_NSP; HEIGHT: 0.6; MFG_NAME01: VISHAY; MFG_PN01: CRCW06030000Z0EAC; ROHS: NULL; Temp Range: –55 °C to +155 °C; VOLTAGE: 1/16W
R14 = RES: RES MF 2.2K 1/16W 1% 0402; 3D_Mechanical_Footprint_File: http://fcl.am.freescale.net/ALLEGRO/step/rc0402_25.STEP; AGILE_PN: 470-83213; CAD_APPROVED: yes; FPLIST: RC0402_25,RC0402_HD,0402_CC; HEIGHT: 0.4mm; MFG_NAME01: Bourns Inc.; MFG_PN01: CR0402-FX-2201GLF; ROHS: NULL; Temp Range: -55 °C to +155 °C; Temp_Range: -55C to +155C
TP10 = TESTLOOP: TEST POINT PAD 30MIL DIA SMT, NO PART TO ORDER; 3D_Mechanical_Footprint_File: http://fcl.am.freescale.net/ALLEGRO/step/tpad_030.STEP; AGILE_PN: 211-76642; CAD_APPROVED: Yes; HEIGHT: 0.1; MFG_NAME01: NOTACOMPONENT; MFG_PN01: NOTACOMPONENT; ROHS: Yes; SILK: XTAL
TP11 = TESTLOOP: TEST POINT PAD 30MIL DIA SMT, NO PART TO ORDER; 3D_Mechanical_Footprint_File: http://fcl.am.freescale.net/ALLEGRO/step/tpad_030.STEP; AGILE_PN: 211-76642; CAD_APPROVED: Yes; HEIGHT: 0.1; MFG_NAME01: NOTACOMPONENT; MFG_PN01: NOTACOMPONENT; ROHS: Yes; SILK: EXTAL
TP12 = TESTLOOP: TEST POINT PAD 40MIL DIA SMT, NO PART TO ORDER; AGILE_PN: 211-10189; CAD_APPROVED: yes; HEIGHT: 0.1MM; MFG_NAME01: NO PART TO ORDER; MFG_PN01: NO PART TO ORDER; ROHS: NULL; SILK: VREFH
TP13 = TESTLOOP: TEST POINT PAD 30MIL DIA SMT, NO PART TO ORDER; 3D_Mechanical_Footprint_File: http://fcl.am.freescale.net/ALLEGRO/step/tpad_030.STEP; AGILE_PN: 211-76642; CAD_APPROVED: Yes; HEIGHT: 0.1; MFG_NAME01: NOTACOMPONENT; MFG_PN01: NOTACOMPONENT; ROHS: Yes; SILK: VRC_CTRL_MCU
TP14 = TESTLOOP: TEST POINT PAD 40MIL DIA SMT, NO PART TO ORDER; AGILE_PN: 211-10189; CAD_APPROVED: yes; HEIGHT: 0.1MM; MFG_NAME01: NO PART TO ORDER; MFG_PN01: NO PART TO ORDER; ROHS: NULL; SILK: VRC_CTRL_F
TP15 = TESTLOOP: TEST POINT PAD 30MIL DIA SMT, NO PART TO ORDER; 3D_Mechanical_Footprint_File: http://fcl.am.freescale.net/ALLEGRO/step/tpad_030.STEP; AGILE_PN: 211-76642; CAD_APPROVED: Yes; HEIGHT: 0.1; MFG_NAME01: NOTACOMPONENT; MFG_PN01: NOTACOMPONENT; ROHS: Yes; SILK: PTB30
TP16 = TESTLOOP: TEST POINT PAD 30MIL DIA SMT, NO PART TO ORDER; 3D_Mechanical_Footprint_File: http://fcl.am.freescale.net/ALLEGRO/step/tpad_030.STEP; AGILE_PN: 211-76642; CAD_APPROVED: Yes; HEIGHT: 0.1; MFG_NAME01: NOTACOMPONENT; MFG_PN01: NOTACOMPONENT; ROHS: Yes; SILK: PTD18
TP17 = TESTLOOP: TEST POINT PAD 30MIL DIA SMT, NO PART TO ORDER; 3D_Mechanical_Footprint_File: http://fcl.am.freescale.net/ALLEGRO/step/tpad_030.STEP; AGILE_PN: 211-76642; CAD_APPROVED: Yes; HEIGHT: 0.1; MFG_NAME01: NOTACOMPONENT; MFG_PN01: NOTACOMPONENT; ROHS: Yes; SILK: PTE19
TP46 = TESTLOOP: TEST POINT PAD 40MIL DIA SMT, NO PART TO ORDER; AGILE_PN: 211-10189; CAD_APPROVED: yes; HEIGHT: 0.1MM; MFG_NAME01: NO PART TO ORDER; MFG_PN01: NO PART TO ORDER; ROHS: NULL; SILK: V25_MCU
TP47 = TESTLOOP: TEST POINT PAD 40MIL DIA SMT, NO PART TO ORDER; AGILE_PN: 211-10189; CAD_APPROVED: yes; HEIGHT: 0.1MM; MFG_NAME01: NO PART TO ORDER; MFG_PN01: NO PART TO ORDER; ROHS: NULL; SILK: V11_MCU
Y1 = XTAL_13: XTAL 16MHz 8pF 15PPM 3225 SMT; 3D_Mechanical_Footprint_File: http://fcl.am.freescale.net/ALLEGRO/step/xtal4_cx3225ca_sm.STEP; AGILE_PN: 230-10068; CAD_APPROVED: Yes; Frequency Tolerance: ±15ppm; HEIGHT: 0.6mm; MFG_NAME01: KYOCERA; MFG_PN01: CX3225SB16000D0GLLCC; Package Size: 3.2 mm x 2.5 mm x 0.6 mm; ROHS: NULL; Temp Range: -30C to +85C
Y2 = CRYSTAL: XTAL 32.768kHz 12.5pF 1.05pF 20ppm SMT; 3D_Mechanical_Footprint_File: http://fcl.am.freescale.net/ALLEGRO/step/xtal2-3p2x1p5-sm.step; AGILE_PN: 230-78676; CAD_APPROVED: Yes; HEIGHT: 0.9; MFG_NAME01: Wurth Electronics Inc.; MFG_PN01: 830009678; ROHS: Yes
R15 R16 = RES: RES MF 4.7K 1/16W 5% 0402; AGILE_PN: 470-75626; CAD_APPROVED: Yes; FPLIST: RC0402_25,RC0402_HD,0402_CC,RC0402_X2; HEIGHT: 0.41; MFG_NAME01: BOURNS; MFG_PN01: CR0402-JW-472GLF; Pkg: 0402; ROHS: NULL; Tolerance: 5%
TP18 = TESTLOOP: TEST POINT PAD 30MIL DIA SMT, NO PART TO ORDER; 3D_Mechanical_Footprint_File: http://fcl.am.freescale.net/ALLEGRO/step/tpad_030.STEP; AGILE_PN: 211-76642; CAD_APPROVED: Yes; HEIGHT: 0.1; MFG_NAME01: NOTACOMPONENT; MFG_PN01: NOTACOMPONENT; ROHS: Yes; SILK: PTD3
TP19 = TESTLOOP: TEST POINT PAD 30MIL DIA SMT, NO PART TO ORDER; 3D_Mechanical_Footprint_File: http://fcl.am.freescale.net/ALLEGRO/step/tpad_030.STEP; AGILE_PN: 211-76642; CAD_APPROVED: Yes; HEIGHT: 0.1; MFG_NAME01: NOTACOMPONENT; MFG_PN01: NOTACOMPONENT; ROHS: Yes; SILK: PTE7
TP20 = TESTLOOP: TEST POINT PAD 30MIL DIA SMT, NO PART TO ORDER; 3D_Mechanical_Footprint_File: http://fcl.am.freescale.net/ALLEGRO/step/tpad_030.STEP; AGILE_PN: 211-76642; CAD_APPROVED: Yes; HEIGHT: 0.1; MFG_NAME01: NOTACOMPONENT; MFG_PN01: NOTACOMPONENT; ROHS: Yes; SILK: PTE13

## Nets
AGND: C25.2 R11.2 U1.17(VREFL) ; also on sheet 13
DGND: C1.2 C2.2 C3.2 C4.2 C5.2 C6.2 C7.2 C8.2 C9.2 C10.2 C11.2 C12.2 C13.2 C14.2 C15.2 C16.2 C17.2 C18.2 C19.2 C20.2 C21.2 C22.2 C23.2 C24.2 C26.2 C27.2 C28.2 C29.2 C30.2 C31.2 C32.2 D4.C(CATHODE) J11.1 J12.1 R11.1 R13.2 TP1.1(Pin1) TP2.1(Pin1) U1.22(VSS_1) U1.24(VSS_2) U1.37(VSS_3) U1.58(VSS_4) U1.78(VSS_5) U1.107(VSS_6) U1.127(VSS_7) U1.150(VSS_8) U1.168(VSS_9) U2.2(VSS) Y1.2 Y1.4 ; also on sheet 7 8 9 10 11 12 13
P3V3: C3.1 C4.1 J10.1 JP2.1 R2.1 TP6.1(Pin1) U2.5(VOUT) ; also on sheet 13
P3V3_BOARD: R2.2 TP8.1(Pin1) ; also on sheet 7 8 9 10 11 12 13
P5V0: C1.1 C2.1 D2.C D3.C J10.3 TP5.1(Pin1) U2.1(CE) U2.4(VIN) ; also on sheet 10 13
P5V_HDR_IN: D3.A ; also on sheet 13
P5V_MCU_LINK: D2.A TP4.1(Pin1) ; also on sheet 7
V11_MCU: C10.1 C11.1 C12.1 C13.1 C14.1 TP47.1(Pin1) U1.21(V11_1) U1.59(V11_2) U1.106(V11_3) U1.149(V11_4)
V15_MCU: C28.1 C29.1 C30.1 C31.1 C32.1 Q1.3(EMITTER) R7.1 R8.1 R9.1 R10.1 R14.2 TP14.1(Pin1)
V25_MCU: C9.1 TP46.1(Pin1) U1.19(V25)
VDD_HV_A_MCU: C15.1 C16.1 C17.1 C18.1 C19.1 C20.1 C26.1 C27.1 JP1.2 Q1.2(COLLECTOR) Q1.4(COLLECTOR1) R6.1 TP7.1(Pin1) U1.18(VDD_HV_A_1) U1.108(VDD_HV_A_2) U1.128(VDD_HV_A_3) U1.151(VDD_HV_A_4) U1.169(VDD_HV_A_5)
VDD_HV_A_MCU_IO_REF: R1.2 R3.1 R15.2 R16.2 TP3.1(Pin1) ; also on sheet 7 8 10 12 13
VDD_HV_B_MCU: C21.1 C22.1 C23.1 C24.1 JP2.2 TP9.1(Pin1) U1.38(VDD_HV_B_1) U1.57(VDD_HV_B_2) U1.77(VDD_HV_B_3)
PIN20_V15: R7.2 R13.1 U1.20(V15_1)
PIN60_V15: R8.2 TP15.1(Pin1) U1.60(V15_2)
PIN105_V15: R9.2 TP16.1(Pin1) U1.105(V15_3)
PIN148_V15: R10.2 TP17.1(Pin1) U1.148(V15_4)
PTA0: U1.137(PTA0/GPIO[0]/LPSPI4_PCS2/eMIOS_0_CH[17]_Y/LCU0_OUT4/FXIO_D2/eMIOS_1_CH[0]_X/LPSPI0_PCS7/TRGMUX_OUT3/LPUART0_CTS/EIRQ[0]/ADC0_S8/CMP1_IN0) ; also on sheet 13
PTA1: U1.135(PTA1/GPIO[1]/LPSPI4_PCS1/eMIOS_0_CH[9]_H/LPUART0_RTS/FXIO_D3/LCU0_OUT5/LPSPI0_PCS6/TRGMUX_OUT0/EIRQ[1]/ADC0_S9/CMP1_IN1/WKPU[5]) ; also on sheet 13
PTA2: U1.124(PTA2/GPIO[2]/FCCU_ERR0/eMIOS_1_CH[19]_Y/FXIO_D4/LCU0_OUT3/LPSPI5_SIN/FCCU_ERR_IN0/LPSPI1_SIN/LPUART0_RX/EIRQ[2]/ADC1_X[0]/WKPU[0]/CMP1_IN2) ; also on sheet 13
PTA3: U1.123(PTA3/GPIO[3]/FCCU_ERR1/eMIOS_1_CH[20]_Y/LPSPI1_SCK/LCU0_OUT2/FXIO_D5/LPUART0_TX/LPSPI5_SCK/FCCU_ERR_IN1/EIRQ[3]/ADC1_S17) ; also on sheet 13
PTA4: U1.170(PTA4/GPIO[4]/FXIO_D6/CMP0_OUT/JTAG_TMS/SWD_DIO/EIRQ[4]/ADC1_S15) ; also on sheet 8
PTA5: U1.167(PTA5/GPIO[5]/RESET_b/EIRQ[5]) ; also on sheet 8 12 13
PTA6: U1.102(PTA6/GPIO[6]/LPSPI1_PCS1/eMIOS_1_CH[13]_H/FXIO_D19/LPSPI3_PCS1/CAN0_RX/LPUART1_CTS/LPUART3_RX/EIRQ[6]/WKPU[15]/ADC0_S18) ; also on sheet 10
PTA7: U1.100(PTA7/GPIO[7]/LPUART3_TX/LPSPI0_PCS1/eMIOS_1_CH[11]_H/CAN0_TX/LPUART1_RTS/FXIO_D9/EIRQ[7]/ADC0_S11) ; also on sheet 10
PTA8: U1.172(PTA8/GPIO[8]/eMIOS_1_CH[12]_H/LPSPI2_SOUT/FXIO_D6/eMIOS_2_CH[7]_H/LPUART2_RX/EIRQ[16]/WKPU[23]/ADC0_P2) ; also on sheet 13
PTA9: U1.171(PTA9/GPIO[9]/LPUART2_TX/LPSPI2_PCS0/FXIO_D7/LPSPI3_PCS0/CMP2_OUT/EIRQ[17]/WKPU[21]/ADC0_P7) ; also on sheet 13
PTA10: U1.161(PTA10/GPIO[10]/eMIOS_0_CH[12]_H/FXIO_D0/JTAG_TDO/TRACEnoETM_SWO/EIRQ[18]) ; also on sheet 8
PTA11: U1.160(PTA11/GPIO[11]/CAN1_TX/eMIOS_0_CH[13]_H/eMIOS_1_CH[1]_H/FXIO_D1/CMP0_RRT/LPSPI1_PCS0/EIRQ[19]/ADC1_S10) ; also on sheet 10
PTA12: U1.159(PTA12/GPIO[12]/LPSPI1_PCS5/eMIOS_0_CH[14]_H/CLKOUT_STANDBY/FXIO_D9/eMIOS_1_CH[2]_H/CMP1_OUT/CAN1_RX/LPUART11_RX/EIRQ[20]/ADC1_P0) ; also on sheet 10
PTA13: U1.155(PTA13/GPIO[13]/LPSPI1_PCS4/eMIOS_0_CH[15]_H/FXIO_D8/eMIOS_1_CH[3]_H/LPUART11_TX/EIRQ[21]/WKPU[4]/ADC1_P1) ; also on sheet 13
PTA14: U1.152(PTA14/GPIO[14]/eMIOS_1_CH[4]_H/LPSPI1_PCS3/eMIOS_2_CH[18]_Y/FXIO_D14/LPSPI5_PCS1/EIRQ[22]/ADC1_P4) ; also on sheet 13
PTA15: U1.145(PTA15/GPIO[15]/eMIOS_0_CH[10]_H/LPSPI0_PCS3/LPSPI2_PCS3/LPSPI5_PCS0/FXIO_D31/LPUART6_RX/EIRQ[23]/ADC1_P7/WKPU[20]) ; also on sheet 13
PTA16: U1.143(PTA16/GPIO[16]/LPSPI4_PCS3/eMIOS_0_CH[11]_H/LPSPI1_PCS2/LPSPI0_PCS4/LPUART6_TX/FXIO_D30/EIRQ[4]/ADC1_S13/WKPU[31]) ; also on sheet 13
PTA17: U1.109(PTA17/GPIO[17]/eMIOS_0_CH[6]_G/LPUART4_TX/LPSPI3_SOUT/FXIO_D19/ADC2_S19) ; also on sheet 13
PTA18: U1.1(PTA18/GPIO[18]/eMIOS_1_CH[0]_X/LPUART1_TX/LPSPI1_SOUT/eMIOS_1_CH[16]_X/eMIOS_2_CH[0]_X/EIRQ[0]/TRGMUX_IN12/ADC2_P0) ; also on sheet 13
PTA19: U1.2(PTA19/GPIO[19]/eMIOS_1_CH[1]_H/LPSPI1_SCK/eMIOS_2_CH[1]_H/LPUART1_RX/EIRQ[1]/TRGMUX_IN13/ADC2_P1) ; also on sheet 13
PTA20: U1.3(PTA20/GPIO[20]/eMIOS_1_CH[2]_H/LPSPI1_SIN/eMIOS_2_CH[2]_H/EIRQ[2]/TRGMUX_IN14/ADC2_P2/WKPU[59]) ; also on sheet 13
PTA21: U1.6(PTA21/GPIO[21]/LPSPI2_PCS2/eMIOS_1_CH[3]_H/FXIO_D0/LPSPI1_PCS0/eMIOS_2_CH[3]_H/EIRQ[3]/TRGMUX_IN15/ADC2_S12) ; also on sheet 13
PTA24: R155.2 U1.14(PTA24/GPI[24]/eMIOS_1_CH[7]_H/FXIO_D3/OSC32K_XTAL)
PTA25: R156.2 U1.15(PTA25/GPI[25]/eMIOS_1_CH[8]_X/eMIOS_2_CH[8]_X/FXIO_D2/EIRQ[5]/OSC32K_EXTAL/WKPU[34])
PTA27: U1.28(PTA27/GPIO[27]/FXIO_D5/eMIOS_1_CH[10]_H/EMAC_PPS1/LPUART0_TX/CAN0_TX/eMIOS_2_CH[10]_H) ; also on sheet 13
PTA28: U1.30(PTA28/GPIO[28]/eMIOS_1_CH[11]_H/LPSPI1_SCK/eMIOS_2_CH[11]_H/CAN0_RX/LPUART0_RX/EIRQ[6]) ; also on sheet 13
PTA29: U1.32(PTA29/GPIO[29]/eMIOS_1_CH[12]_H/EMAC_PPS2/LPUART2_TX/LPSPI1_SIN/eMIOS_2_CH[12]_H) ; also on sheet 13
PTA30: U1.33(PTA30/GPIO[30]/eMIOS_1_CH[13]_H/LPSPI1_SOUT/LPSPI0_SOUT/eMIOS_2_CH[13]_H/LPUART2_RX/EIRQ[7]/WKPU[37]) ; also on sheet 13
PTA31: U1.39(PTA31/GPIO[31]/eMIOS_1_CH[14]_H/FXIO_D0/LPSPI0_PCS1/TRGMUX_OUT8) ; also on sheet 13
PTB0: U1.95(PTB0/GPIO[32]/LPI2C0_SDAS/FXIO_D14/LPSPI0_PCS0/eMIOS_0_CH[3]_G/LCU1_OUT5/eMIOS_1_CH[6]_H/HSE_TAMPER_LOOP_OUT0_/CAN0_RX/LPUART0_RX/EIRQ[8]/ADC1_S14/ADC0_S14/WKPU[7]) ; also on sheet 13
PTB1: U1.94(PTB1/GPIO[33]/LPI2C0_SCLS/LPUART0_TX/LPSPI0_SOUT/eMIOS_0_CH[7]_G/CAN0_TX/eMIOS_1_CH[5]_H/LCU1_OUT4/HSE_TAMPER_EXTIN0/EIRQ[9]/ADC1_S15/ADC0_S15) ; also on sheet 13
PTB2: U1.79(PTB2/GPIO[34]/ADC1_MA[0]/eMIOS_0_CH[8]_X/LPSPI2_SIN/LCU1_OUT3/SAI0_D0/FXIO_D18/CAN4_RX/LPUART9_RX/EIRQ[10]/TRGMUX_IN3/WKPU[8]) ; also on sheet 13
PTB3: U1.74(PTB3/GPIO[35]/LPUART9_TX/eMIOS_0_CH[9]_H/LPSPI2_SOUT/ADC0_MA[0]/CAN4_TX/LCU1_OUT2/FXIO_D17/SAI0_MCLK/EIRQ[11]/TRGMUX_IN2) ; also on sheet 13
PTB4: U1.48(PTB4/GPIO[36]/EMAC_MII_RMII_TXD[1]/eMIOS_0_CH[4]_G/LPSPI0_SOUT/EMAC_MII_RMII_MDIO/eMIOS_1_CH[10]_H/EIRQ[12]/TRGMUX_IN1) ; also on sheet 9
PTB5: U1.47(PTB5/GPIO[37]/EMAC_MII_RMII_TXD[0]/eMIOS_0_CH[5]_G/LPSPI0_PCS1/LPSPI0_PCS0/CLKOUT_RUN/eMIOS_1_CH[11]_H/EMAC_MII_RMII_MDC/EIRQ[13]/TRGMUX_IN0) ; also on sheet 9
PTB8: U1.133(PTB8/GPIO[40]/LPSPI4_PCS0/eMIOS_1_CH[15]_H/LCU0_OUT11/LPSPI0_PCS5/FXIO_D29/EIRQ[14]/CMP2_IN3/ADC0_X[0]/WKPU[25]) ; also on sheet 13
PTB9: U1.130(PTB9/GPIO[41]/LPSPI4_SOUT/eMIOS_1_CH[16]_X/LCU0_OUT10/FXIO_D28/LPUART9_RX/EIRQ[15]/CMP2_IN2/ADC0_X[1]/WKPU[17]) ; also on sheet 13
PTB10: U1.129(PTB10/GPIO[42]/LPSPI4_SCK/eMIOS_1_CH[17]_Y/LPUART9_TX/LCU0_OUT9/FXIO_D27/EIRQ[24]/CMP2_IN1/ADC0_X[2]) ; also on sheet 13
PTB11: U1.126(PTB11/GPIO[43]/LPSPI4_SIN/eMIOS_1_CH[18]_Y/LCU0_OUT8/FXIO_D26/LPI2C0_HREQ/EIRQ[25]/CMP2_IN0/ADC0_X[3]/WKPU[16]) ; also on sheet 13
PTB12: U1.117(PTB12/GPIO[44]/LPSPI3_PCS3/eMIOS_0_CH[0]_X/LCU0_OUT2/FXIO_D25/LPUART8_RX/EIRQ[26]/ADC1_X[1]/WKPU[12]) ; also on sheet 13
PTB13: U1.116(PTB13/GPIO[45]/LPSPI3_PCS2/eMIOS_0_CH[1]_G/FXIO_D8/LCU0_OUT3/LPUART8_TX/FXIO_D24/EIRQ[27]/ADC0_S8/ADC1_S8/ADC2_S8/WKPU[11]) ; also on sheet 13
PTB14: U1.114(PTB14/GPIO[46]/eMIOS_0_CH[2]_G/LPSPI1_SCK/LCU0_OUT7/FXIO_D23/LPUART7_RX/EIRQ[28]/ADC0_S9/ADC1_S9/ADC2_S9) ; also on sheet 13
PTB15: U1.113(PTB15/GPIO[47]/eMIOS_0_CH[3]_G/LPSPI1_SIN/LPUART7_TX/FXIO_D22/EIRQ[29]/ADC1_S11/WKPU[33]) ; also on sheet 13
PTB16: U1.112(PTB16/GPIO[48]/eMIOS_0_CH[4]_G/LPSPI1_SOUT/LPUART4_TX/FXIO_D21/EIRQ[30]/WKPU[13]/ADC1_S12) ; also on sheet 13
PTB17: U1.110(PTB17/GPIO[49]/eMIOS_0_CH[5]_G/LPSPI1_PCS3/eMIOS_1_CH[7]_H/LPSPI3_PCS0/FXIO_D20/LPUART4_RX/EIRQ[31]/ADC1_X[2]/WKPU[14]) ; also on sheet 13
PTB18: U1.42(PTB18/GPIO[50]/LPUART13_TX/eMIOS_1_CH[15]_H/FXIO_D1/LPSPI1_PCS1/eMIOS_2_CH[14]_H/TRGMUX_OUT9) ; also on sheet 13
PTB19: U1.43(PTB19/GPIO[51]/eMIOS_1_CH[15]_H/FXIO_D2/eMIOS_2_CH[15]_H/TRGMUX_OUT10/LPUART13_RX/WKPU[38]) ; also on sheet 13
PTB20: U1.44(PTB20/GPIO[52]/LPUART14_TX/eMIOS_1_CH[16]_X/FXIO_D3/eMIOS_2_CH[16]_X/TRGMUX_OUT11) ; also on sheet 13
PTB21: U1.45(PTB21/GPIO[53]/eMIOS_1_CH[17]_Y/FXIO_D4/eMIOS_2_CH[17]_Y/TRGMUX_OUT12/LPUART14_RX/EIRQ[8]/WKPU[39]) ; also on sheet 13
PTB22: U1.67(PTB22/GPIO[54]/CAN1_TX/eMIOS_1_CH[18]_Y/LPSPI3_PCS1/eMIOS_2_CH[18]_Y/LPUART1_TX/FXIO_D15/TRGMUX_OUT13/EMAC_MII_CRS/EIRQ[9]) ; also on sheet 12 13
PTB23: U1.69(PTB23/GPIO[55]/ADC1_MA[0]/eMIOS_1_CH[19]_Y/FXIO_D4/eMIOS_2_CH[19]_Y/TRGMUX_OUT14/CAN1_RX/EMAC_MII_COL/LPUART1_RX/EIRQ[10]/WKPU[40]) ; also on sheet 12 13
PTB24: U1.70(PTB24/GPIO[56]/ADC1_MA[1]/eMIOS_1_CH[20]_Y/FXIO_D5/eMIOS_2_CH[20]_Y/EIRQ[11]) ; also on sheet 11 13
PTB25: U1.72(PTB25/GPIO[57]/LPUART15_TX/eMIOS_1_CH[21]_Y/FXIO_D6/eMIOS_2_CH[21]_Y/LPSPI2_PCS0/EIRQ[12]) ; also on sheet 13
PTB26: U1.73(PTB26/GPIO[58]/eMIOS_1_CH[22]_X/FXIO_D7/eMIOS_2_CH[22]_X/LPUART15_RX/EIRQ[13]/WKPU[41]) ; also on sheet 13
PTB27: U1.75(PTB27/GPIO[59]/LPUART5_TX/eMIOS_1_CH[23]_X/FXIO_D8/eMIOS_2_CH[23]_X/LPSPI2_SOUT) ; also on sheet 13
PTB28: U1.76(PTB28/GPIO[60]/ADC1_MA[2]/FXIO_D9/eMIOS_2_CH[10]_H/LPSPI2_SIN/LCU1_OUT11/EMAC_PPS3/LPUART5_RX/EIRQ[14]/WKPU[42]) ; also on sheet 13
PTB29: U1.80(PTB29/GPIO[61]/LPUART6_TX/FXIO_D10/eMIOS_2_CH[11]_H/LPSPI2_SCK/LCU1_OUT10/SAI0_D1) ; also on sheet 13
PTC0: U1.62(PTC0/GPIO[64]/CAN3_TX/eMIOS_0_CH[0]_X/EMAC_MII_RMII_RXD[0]/eMIOS_0_CH[14]_H/EMAC_MII_RMII_TX_CLK/EMAC_MII_RMII_RXD[1]/EIRQ[0]) ; also on sheet 9
PTC1: U1.61(PTC1/GPIO[65]/eMIOS_0_CH[1]_G/FXIO_D5/EMAC_MII_RMII_RXD[1]/eMIOS_0_CH[15]_H/CAN3_RX/EMAC_MII_RMII_RXD[0]/EMAC_MII_RX_CLK/EIRQ[1]) ; also on sheet 9
PTC2: U1.50(PTC2/GPIO[66]/EMAC_MII_RMII_TXD[1]/eMIOS_0_CH[2]_G/LPSPI3_PCS2/LPSPI0_PCS2/EMAC_MII_RMII_TXD[0]/TRACE_ETM_CLKOUT/QuadSPI_IOFA3/CAN0_RX/LPUART0_RX/EIRQ[2]/CMP0_IN2) ; also on sheet 8 9 11
PTC3: U1.49(PTC3/GPIO[67]/eMIOS_0_CH[3]_G/CAN0_TX/LPUART0_TX/QuadSPI_PCSFA/EIRQ[3]/CMP0_IN4) ; also on sheet 9 11
PTC4: U1.166(PTC4/GPIO[68]/eMIOS_0_CH[8]_X/FXIO_D5/JTAG_TCK/SWD_CLK/EIRQ[4]/CMP1_IN3) ; also on sheet 8
PTC5: U1.165(PTC5/GPIO[69]/eMIOS_0_CH[16]_X/FXIO_D4/CMP2_RRT/JTAG_TDI/LPI2C1_HREQ/EIRQ[5]/ADC1_S14) ; also on sheet 8
PTC6: R15.1 U1.141(PTC6/GPIO[70]/LPI2C1_SDA/FXIO_D11/LPSPI1_PCS1/LCU0_OUT7/eMIOS_1_CH[6]_H/LPSPI0_PCS1/ADC0_MA[2]/CAN2_RX/LPUART1_RX/EIRQ[6]/WKPU[3]/ADC1_S18) ; also on sheet 13
PTC7: R16.1 U1.140(PTC7/GPIO[71]/FXIO_D10/LPUART1_TX/LPI2C1_SCL/LCU0_OUT6/eMIOS_1_CH[7]_H/LPSPI0_PCS0/CAN2_TX/LPI2C0_HREQ/EIRQ[7]/WKPU[2]/ADC1_S16) ; also on sheet 13
PTC8: U1.98(PTC8/GPIO[72]/LPI2C0_SCL/CAN1_TX/eMIOS_1_CH[9]_H/LCU1_OUT7/LPSPI0_SCK/FXIO_D12/LPUART0_CTS/LPUART1_RX/EIRQ[16]/ADC0_S12) ; also on sheet 13
PTC9: U1.97(PTC9/GPIO[73]/LPI2C0_SDA/LPUART1_TX/LPUART0_RTS/eMIOS_1_CH[8]_X/LCU1_OUT6/LPSPI0_SIN/FXIO_D13/CAN1_RX/EIRQ[17]/ADC0_S13/WKPU[10]) ; also on sheet 13
PTC10: U1.92(PTC10/GPIO[74]/eMIOS_0_CH[6]_G/LPUART11_TX/CAN5_TX/LPSPI2_PCS1/LPSPI4_PCS0/LCU1_OUT11/eMIOS_1_CH[0]_X/EIRQ[18]/TRGMUX_IN11/ADC1_X[3]) ; also on sheet 13
PTC11: U1.90(PTC11/GPIO[75]/eMIOS_1_CH[1]_H/FXIO_D15/LPSPI4_SOUT/FXIO_D19/LCU1_OUT10/CAN5_RX/LPUART11_RX/EIRQ[19]/TRGMUX_IN10/WKPU[18]/ADC0_S17) ; also on sheet 13
PTC12: U1.83(PTC12/GPIO[76]/ADC1_MA[2]/eMIOS_1_CH[2]_H/eMIOS_0_CH[22]_X/LPSPI2_PCS1/FXIO_D19/LCU1_OUT9/SAI0_BCLK/LPUART10_RX/EIRQ[20]) ; also on sheet 13
PTC13: U1.81(PTC13/GPIO[77]/LPUART10_TX/eMIOS_1_CH[3]_H/eMIOS_0_CH[23]_X/ADC1_MA[1]/FXIO_D16/LCU1_OUT8/SAI0_SYNC/EIRQ[21]) ; also on sheet 13
PTC14: U1.71(PTC14/GPIO[78]/eMIOS_0_CH[10]_H/LPSPI2_PCS0/ADC0_MA[1]/eMIOS_1_CH[4]_H/LCU1_OUT1/FXIO_D16/CAN2_RX/EMAC_MII_COL/EMAC_MII_RMII_RX_ER/EMAC_MII_RXD3/EIRQ[22]/TRGMUX_IN9) ; also on sheet 12
PTC15: U1.68(PTC15/GPIO[79]/CAN2_TX/eMIOS_0_CH[11]_H/LPSPI2_SCK/ADC0_MA[2]/LPUART2_TX/LCU1_OUT0/LPI2C1_SCL/EMAC_MII_CRS/EMAC_MII_RMII_RX_DV/EMAC_MII_RXD2/EIRQ[23]/TRGMUX_IN8) ; also on sheet 11 13
PTC16: U1.66(PTC16/GPIO[80]/LPSPI3_SIN/eMIOS_1_CH[9]_H/eMIOS_2_CH[9]_H/LPI2C1_SDAS/FXIO_D15/LPI2C1_SDA/CAN2_RX/EMAC_MII_RMII_RX_ER/LPUART2_RX) ; also on sheet 12 13
PTC17: U1.65(PTC17/GPIO[81]/LPSPI3_SCK/CAN2_TX/LPI2C1_SCLS/EMAC_MII_RMII_RX_DV/FXIO_D14) ; also on sheet 9
PTC18: U1.82(PTC18/GPIO[82]/FXIO_D6/FXIO_D12/eMIOS_2_CH[12]_H/LCU1_OUT7/SAI0_D2/LPUART6_RX/WKPU[36]) ; also on sheet 13
PTC19: U1.84(PTC19/GPIO[83]/LPUART7_TX/FXIO_D13/eMIOS_2_CH[13]_H/LPSPI2_PCS1/LCU1_OUT6/SAI0_D3) ; also on sheet 13
PTC20: U1.85(PTC20/GPIO[84]/FXIO_D14/eMIOS_2_CH[14]_H/ADC1_MA[2]/LCU1_OUT5/LPUART7_RX/EIRQ[16]/WKPU[43]) ; also on sheet 13
PTC21: U1.86(PTC21/GPIO[85]/FXIO_D15/eMIOS_2_CH[15]_H/ADC1_MA[1]/LCU1_OUT4/EIRQ[17]) ; also on sheet 13
PTC23: U1.87(PTC23/GPIO[87]/FXIO_D16/LCU1_OUT0/EIRQ[18]/WKPU[44]/ADC2_S23) ; also on sheet 13
PTC24: U1.88(PTC24/GPIO[88]/LPUART12_TX/eMIOS_1_CH[0]_X/FXIO_D17/eMIOS_2_CH[0]_X/LCU1_OUT1/TRGMUX_OUT15/EIRQ[19]/ADC2_S22/WKPU[46]) ; also on sheet 13
PTC25: U1.89(PTC25/GPIO[89]/eMIOS_1_CH[1]_H/FXIO_D18/eMIOS_2_CH[1]_H/LPSPI4_PCS1/LCU1_OUT2/LPUART12_RX/EIRQ[20]/ADC0_S20/WKPU[45]) ; also on sheet 13
PTC26: U1.91(PTC26/GPIO[90]/LPUART13_TX/eMIOS_1_CH[3]_H/FXIO_D19/eMIOS_2_CH[2]_H/LCU1_OUT9/LPSPI4_SIN/CAN5_RX/EIRQ[21]/ADC0_S21/WKPU[48]) ; also on sheet 13
PTC27: U1.93(PTC27/GPIO[91]/CAN5_TX/eMIOS_1_CH[4]_H/FXIO_D20/eMIOS_2_CH[3]_H/ADC1_MA[0]/LCU1_OUT3/LPSPI4_SCK/LPUART13_RX/EIRQ[22]) ; also on sheet 13
PTC28: U1.96(PTC28/GPIO[92]/CAN3_TX/eMIOS_1_CH[7]_H/FXIO_D21/FXIO_D2/LPI2C1_SCL/LCU1_OUT8) ; also on sheet 13
PTC29: U1.99(PTC29/GPIO[93]/eMIOS_1_CH[10]_H/FXIO_D22/eMIOS_2_CH[4]_H/LPI2C1_SDA/FXIO_D3/CAN3_RX/EIRQ[23]/WKPU[47]) ; also on sheet 13
PTC30: U1.101(PTC30/GPIO[94]/CAN4_TX/eMIOS_1_CH[12]_H/FXIO_D0/eMIOS_2_CH[5]_H/FXIO_D23) ; also on sheet 13
PTC31: U1.103(PTC31/GPIO[95]/eMIOS_1_CH[14]_H/FXIO_D1/eMIOS_2_CH[6]_H/FXIO_D24/CAN4_RX/ADC2_S21/WKPU[49]) ; also on sheet 13
PTD0: U1.8(PTD0/GPIO[96]/eMIOS_0_CH[2]_G/LPSPI3_SOUT/eMIOS_0_CH[16]_X/FXIO_D0/TRGMUX_OUT1/LPUART5_RX/EIRQ[8]/WKPU[6]/ADC0_P1) ; also on sheet 13
PTD1: U1.7(PTD1/GPIO[97]/LPUART5_TX/eMIOS_0_CH[3]_G/LPSPI3_SCK/eMIOS_0_CH[17]_Y/FXIO_D1/TRGMUX_OUT2/EIRQ[9]/ADC0_P0) ; also on sheet 13
PTD2: U1.121(PTD2/GPIO[98]/LCU0_OUT1/eMIOS_1_CH[21]_Y/LPSPI1_SOUT/FXIO_D4/FXIO_D6/LPUART3_TX/LPSPI5_SOUT/EIRQ[10]/TRGMUX_IN5/WKPU[9]/ADC0_S16) ; also on sheet 13
PTD3: TP18.1(Pin1) U1.120(PTD3/GPIO[99]/eMIOS_1_CH[22]_X/LPSPI1_PCS0/FXIO_D5/FXIO_D7/LCU0_OUT0/LPUART3_RX/EIRQ[11]/TRGMUX_IN4/NMI_b/WKPU[1]/ADC0_S10)
PTD4: U1.119(PTD4/GPIO[100]/eMIOS_1_CH[23]_X/LPSPI1_PCS1/LCU0_OUT6/LPSPI5_PCS0/EIRQ[12]/ADC0_S19/WKPU[22]) ; also on sheet 13
PTD5: U1.53(PTD5/GPIO[101]/EMAC_MII_TXD2/eMIOS_0_CH[19]_Y/eMIOS_0_CH[2]_G/EMAC_MII_TXD3/FXIO_D15/LPSPI0_PCS1/EMAC_MII_RX_CLK/EIRQ[13]/TRGMUX_IN7) ; also on sheet 11 12
PTD6: U1.52(PTD6/GPIO[102]/EMAC_MII_TXD3/eMIOS_1_CH[12]_H/EMAC_MII_RMII_TX_CLK/EMAC_MII_TXD2/FXIO_D13/LPSPI0_PCS0/LPUART2_RX/EIRQ[14]/CMP0_IN7) ; also on sheet 13
PTD7: U1.51(PTD7/GPIO[103]/EMAC_MII_RMII_TXD[0]/LPUART2_TX/LPSPI3_PCS3/LPSPI0_PCS3/EMAC_MII_RMII_TXD[1]/TRACE_ETM_D0/QuadSPI_IOFA1/EIRQ[15]/CMP0_IN6) ; also on sheet 8 9 11
PTD8: U1.64(PTD8/GPIO[104]/LPSPI3_SOUT/LPI2C1_SDA/EMAC_MII_RXD3/FXIO_D1/eMIOS_0_CH[12]_H/FXIO_D11/EMAC_MII_RMII_RXD[1]/LPUART6_RX/EIRQ[24]) ; also on sheet 13
PTD9: U1.63(PTD9/GPIO[105]/EMAC_MII_RXD2/LPI2C1_SCL/FXIO_D0/LPUART6_TX/eMIOS_0_CH[13]_H/FXIO_D10/EMAC_MII_RMII_RXD[0]/EIRQ[25]) ; also on sheet 13
PTD10: U1.56(PTD10/GPIO[106]/EMAC_MII_TXD3/eMIOS_0_CH[16]_X/eMIOS_1_CH[10]_H/TRACE_ETM_D3/LPSPI0_SIN/CLKOUT_RUN/QuadSPI_SCKFA/EMAC_MII_RX_CLK/EIRQ[26]) ; also on sheet 8 11
PTD11: U1.55(PTD11/GPIO[107]/EMAC_MII_TXD2/eMIOS_0_CH[17]_Y/EMAC_MII_RMII_TX_EN/TRACE_ETM_D2/EMAC_MII_RMII_TX_CLK/LPSPI0_SCK/QuadSPI_IOFA0/LPUART2_CTS/EIRQ[27]) ; also on sheet 8 9 11
PTD12: U1.54(PTD12/GPIO[108]/EMAC_MII_RMII_TX_CLK/eMIOS_0_CH[18]_Y/LPUART2_RTS/TRACE_ETM_D1/EMAC_MII_RMII_TX_EN/LPSPI0_SOUT/QuadSPI_IOFA2/LPI2C1_HREQ/EIRQ[28]) ; also on sheet 8 9 11
PTD13: U1.41(PTD13/GPIO[109]/LPSPI5_SIN/eMIOS_0_CH[20]_Y/FXIO_D7/LPI2C0_SDA/EMAC_PPS1/SAI1_D0/LPUART1_RX/EIRQ[29]/WKPU[24]) ; also on sheet 8 11 13
PTD14: U1.40(PTD14/GPIO[110]/LPSPI5_SCK/eMIOS_0_CH[21]_Y/LPUART1_TX/LPI2C0_SCL/EMAC_PPS0/CMP0_RRT/CLKOUT_RUN/SAI1_MCLK/EIRQ[30]) ; also on sheet 8 11 13
PTD15: U1.35(PTD15/GPIO[111]/FXIO_D6/eMIOS_0_CH[0]_X/eMIOS_1_CH[14]_H/LPSPI0_SCK/EMAC_PPS2/SAI1_SYNC/FXIO_D10/CAN3_RX/LPUART2_CTS/LPUART8_RX/EIRQ[31]/CMP0_IN1) ; also on sheet 13
PTD16: U1.34(PTD16/GPIO[112]/eMIOS_0_CH[1]_G/EMAC_MII_RMII_MDIO/LPSPI0_SIN/eMIOS_1_CH[15]_H/LPUART2_RTS/LPUART8_TX/CMP0_IN5) ; also on sheet 13
PTD17: U1.31(PTD17/GPIO[113]/LPSPI5_PCS0/eMIOS_0_CH[18]_Y/EMAC_MII_RMII_MDC/LPSPI3_PCS0/FXIO_D9/EMAC_PPS2/CAN5_RX/LPUART2_RX/EIRQ[24]) ; also on sheet 13
PTD20: U1.111(PTD20/GPIO[116]/eMIOS_1_CH[17]_Y/FXIO_D25/eMIOS_2_CH[0]_X/LPSPI1_PCS2/LPSPI3_SIN/EIRQ[25]/ADC0_S22/WKPU[54]) ; also on sheet 13
PTD21: U1.115(PTD21/GPIO[117]/eMIOS_1_CH[18]_Y/FXIO_D26/eMIOS_2_CH[8]_X/LCU0_OUT4/EIRQ[26]/ADC0_S23) ; also on sheet 13
PTD22: U1.118(PTD22/GPIO[118]/eMIOS_1_CH[19]_Y/FXIO_D27/eMIOS_2_CH[22]_X/LCU0_OUT5/EIRQ[27]/ADC2_S18) ; also on sheet 13
PTD23: U1.122(PTD23/GPIO[119]/eMIOS_1_CH[20]_Y/FXIO_D28/eMIOS_2_CH[23]_X/HSE_TAMPER_LOOP_OUT0_/LCU0_OUT10/EIRQ[28]/WKPU[50]/ADC2_S17) ; also on sheet 13
PTD24: U1.125(PTD24/GPIO[120]/eMIOS_1_CH[21]_Y/FXIO_D29/LCU0_OUT11/HSE_TAMPER_EXTIN0/EIRQ[29]/ADC1_S20) ; also on sheet 13
PTD26: U1.131(PTD26/GPIO[122]/LPUART14_TX/eMIOS_1_CH[23]_X/FXIO_D7/eMIOS_2_CH[7]_H/FXIO_D30/LPSPI5_SCK/LCU0_OUT0/ADC2_S16) ; also on sheet 13
PTD27: U1.132(PTD27/GPIO[123]/eMIOS_2_CH[9]_H/FXIO_D31/LPSPI5_SOUT/LCU0_OUT1/LPUART14_RX/EIRQ[30]/ADC1_S21/WKPU[51]) ; also on sheet 13
PTD28: U1.134(PTD28/GPIO[124]/LPUART15_TX/eMIOS_2_CH[0]_X/LCU0_OUT2/LPSPI5_SIN/EIRQ[31]/ADC1_S22) ; also on sheet 13
PTD29: U1.136(PTD29/GPIO[125]/eMIOS_2_CH[8]_X/LCU0_OUT3/LPSPI5_PCS2/LPUART15_RX/ADC1_S23/WKPU[52]) ; also on sheet 13
PTD30: U1.138(PTD30/GPIO[126]/eMIOS_2_CH[16]_X/LCU0_OUT8/LPSPI5_PCS3/ADC2_S15) ; also on sheet 13
PTD31: U1.139(PTD31/GPIO[127]/FXIO_D6/eMIOS_2_CH[22]_X/LCU0_OUT9/WKPU[53]/ADC2_S14) ; also on sheet 13
PTE0: U1.163(PTE0/GPIO[128]/LPSPI0_SIN/FXIO_D3/LPUART7_RX/EIRQ[0]/WKPU[26]/ADC1_P2) ; also on sheet 13
PTE1: U1.162(PTE1/GPIO[129]/LPSPI0_SCK/FXIO_D2/LPUART7_TX/EIRQ[1]/ADC1_P3) ; also on sheet 13
PTE2: U1.147(PTE2/GPIO[130]/LPSPI0_SOUT/eMIOS_0_CH[3]_G/eMIOS_1_CH[8]_X/FXIO_D13/ADC0_MA[0]/LPUART1_CTS/LPUART10_RX/EIRQ[2]/WKPU[27]/ADC1_P5) ; also on sheet 13
PTE3: U1.27(PTE3/GPIO[131]/CAN4_TX/eMIOS_0_CH[19]_Y/FXIO_D6/LPUART2_RTS/EMAC_PPS0/CMP0_OUT/LPUART5_RX/EIRQ[3]/TRGMUX_IN6) ; also on sheet 8 13
PTE4: U1.13(PTE4/GPIO[132]/LPSPI0_PCS0/LPSPI1_PCS1/eMIOS_1_CH[4]_H/eMIOS_0_CH[18]_Y/LPUART12_TX/FXIO_D6/EIRQ[4]/ADC2_S9) ; also on sheet 13
PTE5: U1.12(PTE5/GPIO[133]/eMIOS_1_CH[5]_H/eMIOS_0_CH[19]_Y/FXIO_D7/LPUART12_RX/EIRQ[5]/ADC2_S8/WKPU[32]) ; also on sheet 13
PTE6: U1.146(PTE6/GPIO[134]/LPSPI0_PCS2/LPUART1_RTS/eMIOS_1_CH[14]_H/LPUART10_TX/FXIO_D12/ADC0_MA[1]/EIRQ[6]/ADC1_P6/WKPU[29]) ; also on sheet 13
PTE7: TP19.1(Pin1) U1.104(PTE7/GPIO[135]/eMIOS_0_CH[7]_G/LPSPI3_SCK/FXIO_D11/LPUART4_RX/ADC2_S20)
PTE8: U1.46(PTE8/GPIO[136]/LPSPI3_PCS1/eMIOS_0_CH[6]_G/LPSPI5_PCS1/FXIO_D12/EMAC_MII_RMII_MDC/SAI1_BCLK/FXIO_D8/EIRQ[7]/CMP0_IN3) ; also on sheet 13
PTE9: U1.36(PTE9/GPIO[137]/LPSPI5_SOUT/eMIOS_0_CH[7]_G/eMIOS_1_CH[13]_H/CAN3_TX/EMAC_PPS3/EMAC_MII_RMII_TX_EN/FXIO_D11/LPUART2_CTS/EIRQ[8]/CMP0_IN0) ; also on sheet 13
PTE10: U1.10(PTE10/GPIO[138]/LPSPI3_SIN/LPSPI2_PCS1/eMIOS_0_CH[20]_Y/CLKOUT_STANDBY/FXIO_D4/TRGMUX_OUT4/LPUART4_RX/EIRQ[9]/ADC0_P5) ; also on sheet 13
PTE11: U1.9(PTE11/GPIO[139]/LPUART4_TX/LPSPI2_PCS0/eMIOS_0_CH[1]_G/eMIOS_0_CH[21]_Y/FXIO_D5/TRGMUX_OUT5/EIRQ[10]/WKPU[28]/ADC0_P6) ; also on sheet 13
PTE12: U1.29(PTE12/GPIO[140]/CAN5_TX/LPUART2_TX/eMIOS_1_CH[5]_H/EMAC_PPS3/FXIO_D8/EIRQ[11]) ; also on sheet 13
PTE13: R12.1 TP20.1(Pin1) U1.11(PTE13/GPIO[141]/eMIOS_1_CH[5]_H/LPSPI2_PCS2/LPSPI2_PCS0/FXIO_D5/EIRQ[12]/VRC_CTRL/ADC1_S19)
PTE14: U1.26(PTE14/GPIO[142]/eMIOS_0_CH[19]_Y/LPUART5_TX/FXIO_D7/EMAC_PPS1/CAN4_RX/EIRQ[13]/WKPU[30]) ; also on sheet 8 13
PTE15: U1.5(PTE15/GPIO[143]/FCCU_ERR0/LPSPI2_SCK/eMIOS_0_CH[22]_X/CMP1_RRT/FXIO_D2/TRGMUX_OUT6/FCCU_ERR_IN0/LPUART1_CTS/LPUART3_RX/EIRQ[14]/ADC0_P3) ; also on sheet 13
PTE16: U1.4(PTE16/GPIO[144]/FCCU_ERR1/LPUART3_TX/LPSPI2_SIN/eMIOS_0_CH[23]_X/LPUART1_RTS/FXIO_D3/TRGMUX_OUT7/FCCU_ERR_IN1/EIRQ[15]/ADC0_P4/WKPU[19]) ; also on sheet 13
PTE17: U1.142(PTE17/GPIO[145]/FXIO_D5/eMIOS_2_CH[23]_X/ADC2_S10/ADC1_S22) ; also on sheet 13
PTE18: U1.144(PTE18/GPIO[146]/FXIO_D4/eMIOS_2_CH[17]_Y/ADC2_S11/WKPU[55]/ADC1_S23) ; also on sheet 13
PTE21: U1.153(PTE21/GPIO[149]/eMIOS_1_CH[1]_H/eMIOS_2_CH[19]_Y/LPSPI4_SIN/WKPU[56]/ADC2_P3) ; also on sheet 13
PTE22: U1.154(PTE22/GPIO[150]/eMIOS_1_CH[2]_H/eMIOS_2_CH[20]_Y/LPSPI4_SCK/ADC2_P4) ; also on sheet 13
PTE23: U1.156(PTE23/GPIO[151]/eMIOS_1_CH[3]_H/eMIOS_2_CH[21]_Y/LPSPI4_PCS0/WKPU[57]/ADC2_P5) ; also on sheet 13
PTE24: U1.157(PTE24/GPIO[152]/eMIOS_1_CH[4]_H/CAN2_TX/eMIOS_2_CH[4]_H/FXIO_D5/LPSPI4_PCS1/FXIO_D11/ADC2_S13) ; also on sheet 10
PTE25: U1.158(PTE25/GPIO[153]/eMIOS_1_CH[5]_H/eMIOS_2_CH[5]_H/LPSPI4_SOUT/CAN2_RX/WKPU[58]/ADC2_P7) ; also on sheet 10
PTE26: U1.164(PTE26/GPIO[154]/eMIOS_1_CH[6]_H/eMIOS_2_CH[6]_H/ADC2_P6) ; also on sheet 13
VREFH_MCU: C25.1 R6.2 TP12.1(Pin1) U1.16(VREFH) ; also on sheet 13
N18196621: D4.A(ANODE) R3.2
N18478534: J10.2 JP1.1 R1.1
N18578148: C5.1 R4.1 TP10.1(Pin1) Y1.3
N18578152: C6.1 R5.1 TP11.1(Pin1) Y1.1
N18579923: R4.2 U1.25(XTAL)
N18579959: R5.2 U1.23(EXTAL)
N18599907: Q1.1(BASE) R12.2 R14.1 TP13.1(Pin1)
N18626341: C7.1 R155.1 Y2.2
N18626346: C8.1 R156.1 Y2.1

Not connected (* = marked no-connect by the designer): BH1 1*; BH2 1*; BH3 1*; BH4 1*; U2 3(NC)*

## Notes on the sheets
sheet 1
- Revision History
- Table of Contents
- REV
- REVISION NOTES
- Date
- 01
- TITLE PAGE
- A
- Based on FRDM-MCXE318(95159, Ver.B) to update MCU MPN.
- Mar 13, 2025
- 02
- BLOCK DIAGRAM
- A1
- 1.DNP R52.
  2.Change CAN PHY from TJA1057GTK/3Z  to TJA1057BTK.
    No change for layout.
- May 30, 2025
- 03
- POWER
- 04
- MCU_AB
- 05
- MCU_C
- 06
- MCU_PORT
- 07
- MCU_LINK
- 08
- MCU_LINK_DEBUG
- 09
- ETHERNET
- 10
- CAN
- 11
- QSPI FLASH & SENSOR
- 12
- SWITCH & LED
- 13
- HEADERS
- 14
- APPENDIX JUMPER/DNP
- FRDM-MCXE31B
sheet 2
- BLOCK DIAGRAM
sheet 3
- LDO
- 5V
- 3.3V
- Note:
  MCXE31B(Default): supports both 3.3V and 5V power supply.
  When powered by 5V, the on-board Ethernet PHY,
  Sensors (FXLS8974CFR3 and NMH1000),
  and MCU-LINK can all communicate normally.
- MCXE317: Only 3.3V supply is supported.
  5V supply is not supported.
- POWER LED
- GND TEST POINTS
- POWER TEST POINTS
- MOUNTING HOLES
- Note:
  The mechanical mounting holes are
  placed on the four vertices of the board
sheet 5
- CLOCK
- V25
- V11
- VDD_HV_A
- VDD_HV_B
- VREFH
- C25 is the off-chip decoupling capacitor
  between the VREFH pin and the VSS/VREFL, it
  should be placed between pin 16 and pin 17.
- V15
- AGND&DGND
- External NPN Ballast
  Transistor V15
- Note:
  E31B: connect PIN20/60/105/148 with V15_MCU(Default)
  E317: disconnect PIN20/60/105/148 with V15_MCU
sheet 6
- PORT-A
- PORT-B
- PORT-C
- PORT-D
- PORT-E
